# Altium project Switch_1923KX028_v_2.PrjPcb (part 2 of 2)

## Sheet switch_1923KX028_v_2_sheet_6.SchDoc
size A3; DocumentNumber: 7; SheetNumber: 7; SheetTotal: 10
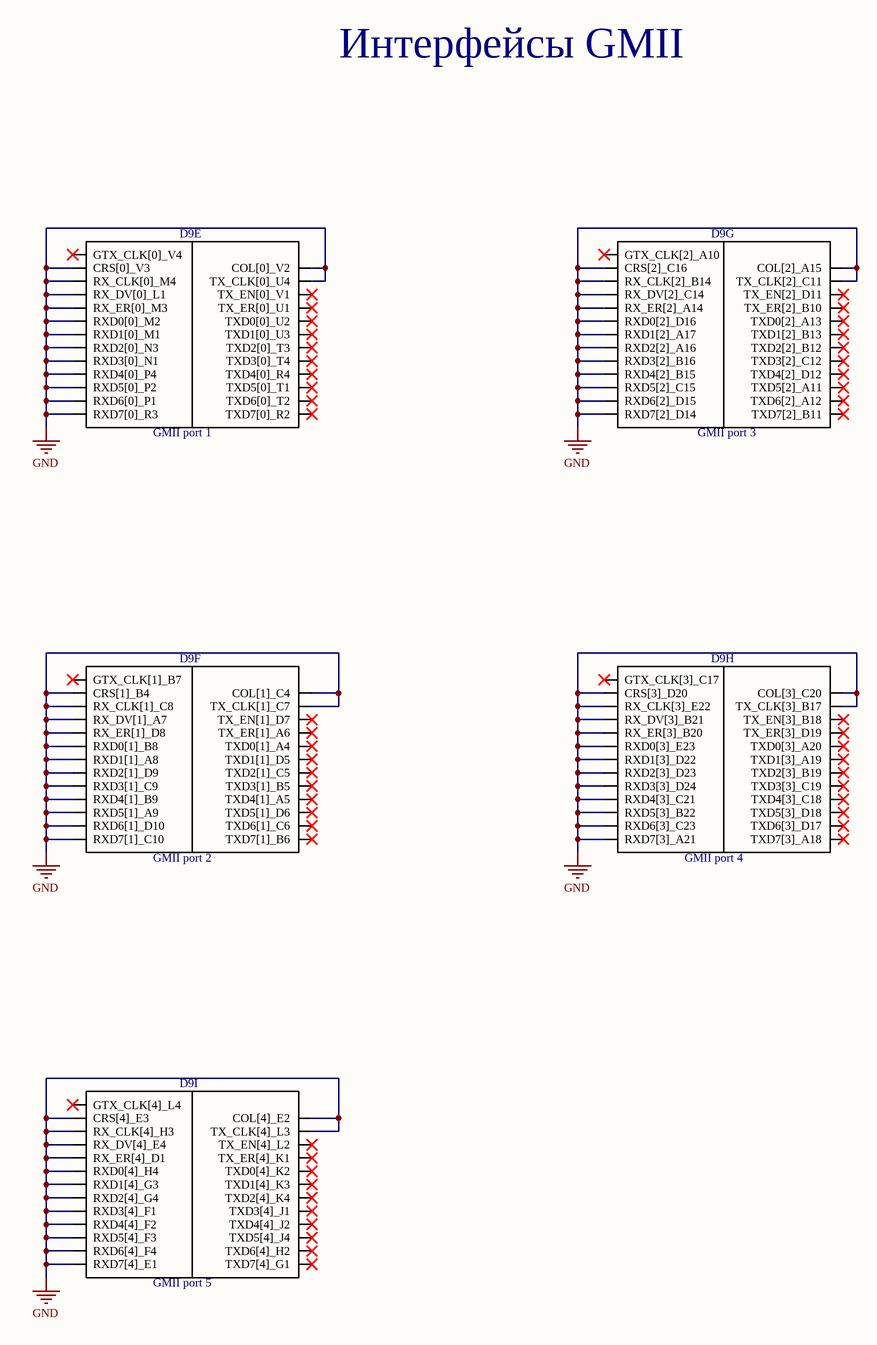
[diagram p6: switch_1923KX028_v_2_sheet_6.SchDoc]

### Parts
D9  1923KX028  [FOOTPRINT_MK8303.576-1]  (value not drawn)  (parts E,F,G,H,I of 27)

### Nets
GND: D9.A7(RX_DV[1]_A7) D9.A8(RXD1[1]_A8) D9.A9(RXD5[1]_A9) D9.A14(RX_ER[2]_A14) D9.A15(COL[2]_A15) D9.A16(RXD2[2]_A16) D9.A17(RXD1[2]_A17) D9.A21(RXD7[3]_A21) D9.B4(CRS[1]_B4) D9.B8(RXD0[1]_B8) D9.B9(RXD4[1]_B9) D9.B14(RX_CLK[2]_B14) D9.B15(RXD4[2]_B15) D9.B16(RXD3[2]_B16) D9.B17(TX_CLK[3]_B17) D9.B20(RX_ER[3]_B20) D9.B21(RX_DV[3]_B21) D9.B22(RXD5[3]_B22) D9.C4(COL[1]_C4) D9.C7(TX_CLK[1]_C7) D9.C8(RX_CLK[1]_C8) D9.C9(RXD3[1]_C9) D9.C10(RXD7[1]_C10) D9.C11(TX_CLK[2]_C11) D9.C14(RX_DV[2]_C14) D9.C15(RXD5[2]_C15) D9.C16(CRS[2]_C16) D9.C20(COL[3]_C20) D9.C21(RXD4[3]_C21) D9.C23(RXD6[3]_C23) D9.D1(RX_ER[4]_D1) D9.D8(RX_ER[1]_D8) D9.D9(RXD2[1]_D9) D9.D10(RXD6[1]_D10) D9.D14(RXD7[2]_D14) D9.D15(RXD6[2]_D15) D9.D16(RXD0[2]_D16) D9.D20(CRS[3]_D20) D9.D22(RXD1[3]_D22) D9.D23(RXD2[3]_D23) D9.D24(RXD3[3]_D24) D9.E1(RXD7[4]_E1) D9.E2(COL[4]_E2) D9.E3(CRS[4]_E3) D9.E4(RX_DV[4]_E4) D9.E22(RX_CLK[3]_E22) D9.E23(RXD0[3]_E23) D9.F1(RXD3[4]_F1) D9.F2(RXD4[4]_F2) D9.F3(RXD5[4]_F3) D9.F4(RXD6[4]_F4) D9.G3(RXD1[4]_G3) D9.G4(RXD2[4]_G4) D9.H3(RX_CLK[4]_H3) D9.H4(RXD0[4]_H4) D9.L1(RX_DV[0]_L1) D9.L3(TX_CLK[4]_L3) D9.M1(RXD1[0]_M1) D9.M2(RXD0[0]_M2) D9.M3(RX_ER[0]_M3) D9.M4(RX_CLK[0]_M4) D9.N1(RXD3[0]_N1) D9.N3(RXD2[0]_N3) D9.P1(RXD6[0]_P1) D9.P2(RXD5[0]_P2) D9.P4(RXD4[0]_P4) D9.R3(RXD7[0]_R3) D9.U4(TX_CLK[0]_U4) D9.V2(COL[0]_V2) D9.V3(CRS[0]_V3)

Not connected (* = marked no-connect by the designer): D9 A4(TXD0[1]_A4)* A5(TXD4[1]_A5)* A6(TX_ER[1]_A6)* A10(GTX_CLK[2]_A10)* A11(TXD5[2]_A11)* A12(TXD6[2]_A12)* A13(TXD0[2]_A13)* A18(TXD7[3]_A18)* A19(TXD1[3]_A19)* A20(TXD0[3]_A20)* B5(TXD3[1]_B5)* B6(TXD7[1]_B6)* B7(GTX_CLK[1]_B7)* B10(TX_ER[2]_B10)* B11(TXD7[2]_B11)* B12(TXD2[2]_B12)* B13(TXD1[2]_B13)* B18(TX_EN[3]_B18)* B19(TXD2[3]_B19)* C5(TXD2[1]_C5)* C6(TXD6[1]_C6)* C12(TXD3[2]_C12)* C17(GTX_CLK[3]_C17)* C18(TXD4[3]_C18)* C19(TXD3[3]_C19)* D5(TXD1[1]_D5)* D6(TXD5[1]_D6)* D7(TX_EN[1]_D7)* D11(TX_EN[2]_D11)* D12(TXD4[2]_D12)* D17(TXD6[3]_D17)* D18(TXD5[3]_D18)* D19(TX_ER[3]_D19)* G1(TXD7[4]_G1)* H2(TXD6[4]_H2)* J1(TXD3[4]_J1)* J2(TXD4[4]_J2)* J4(TXD5[4]_J4)* K1(TX_ER[4]_K1)* K2(TXD0[4]_K2)* K3(TXD1[4]_K3)* K4(TXD2[4]_K4)* L2(TX_EN[4]_L2)* L4(GTX_CLK[4]_L4)* R2(TXD7[0]_R2)* R4(TXD4[0]_R4)* T1(TXD5[0]_T1)* T2(TXD6[0]_T2)* T3(TXD2[0]_T3)* T4(TXD3[0]_T4)* U1(TX_ER[0]_U1)* U2(TXD0[0]_U2)* U3(TXD1[0]_U3)* V1(TX_EN[0]_V1)* V4(GTX_CLK[0]_V4)*

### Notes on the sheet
- Интерфейсы GMII

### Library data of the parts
D9 = 1923KX028: Milandr, 16 ports Ethernet Switch 1000/100/10

## Sheet switch_1923KX028_v_2_sheet_7.SchDoc
size A3; DocumentNumber: 8; SheetNumber: 8; SheetTotal: 10
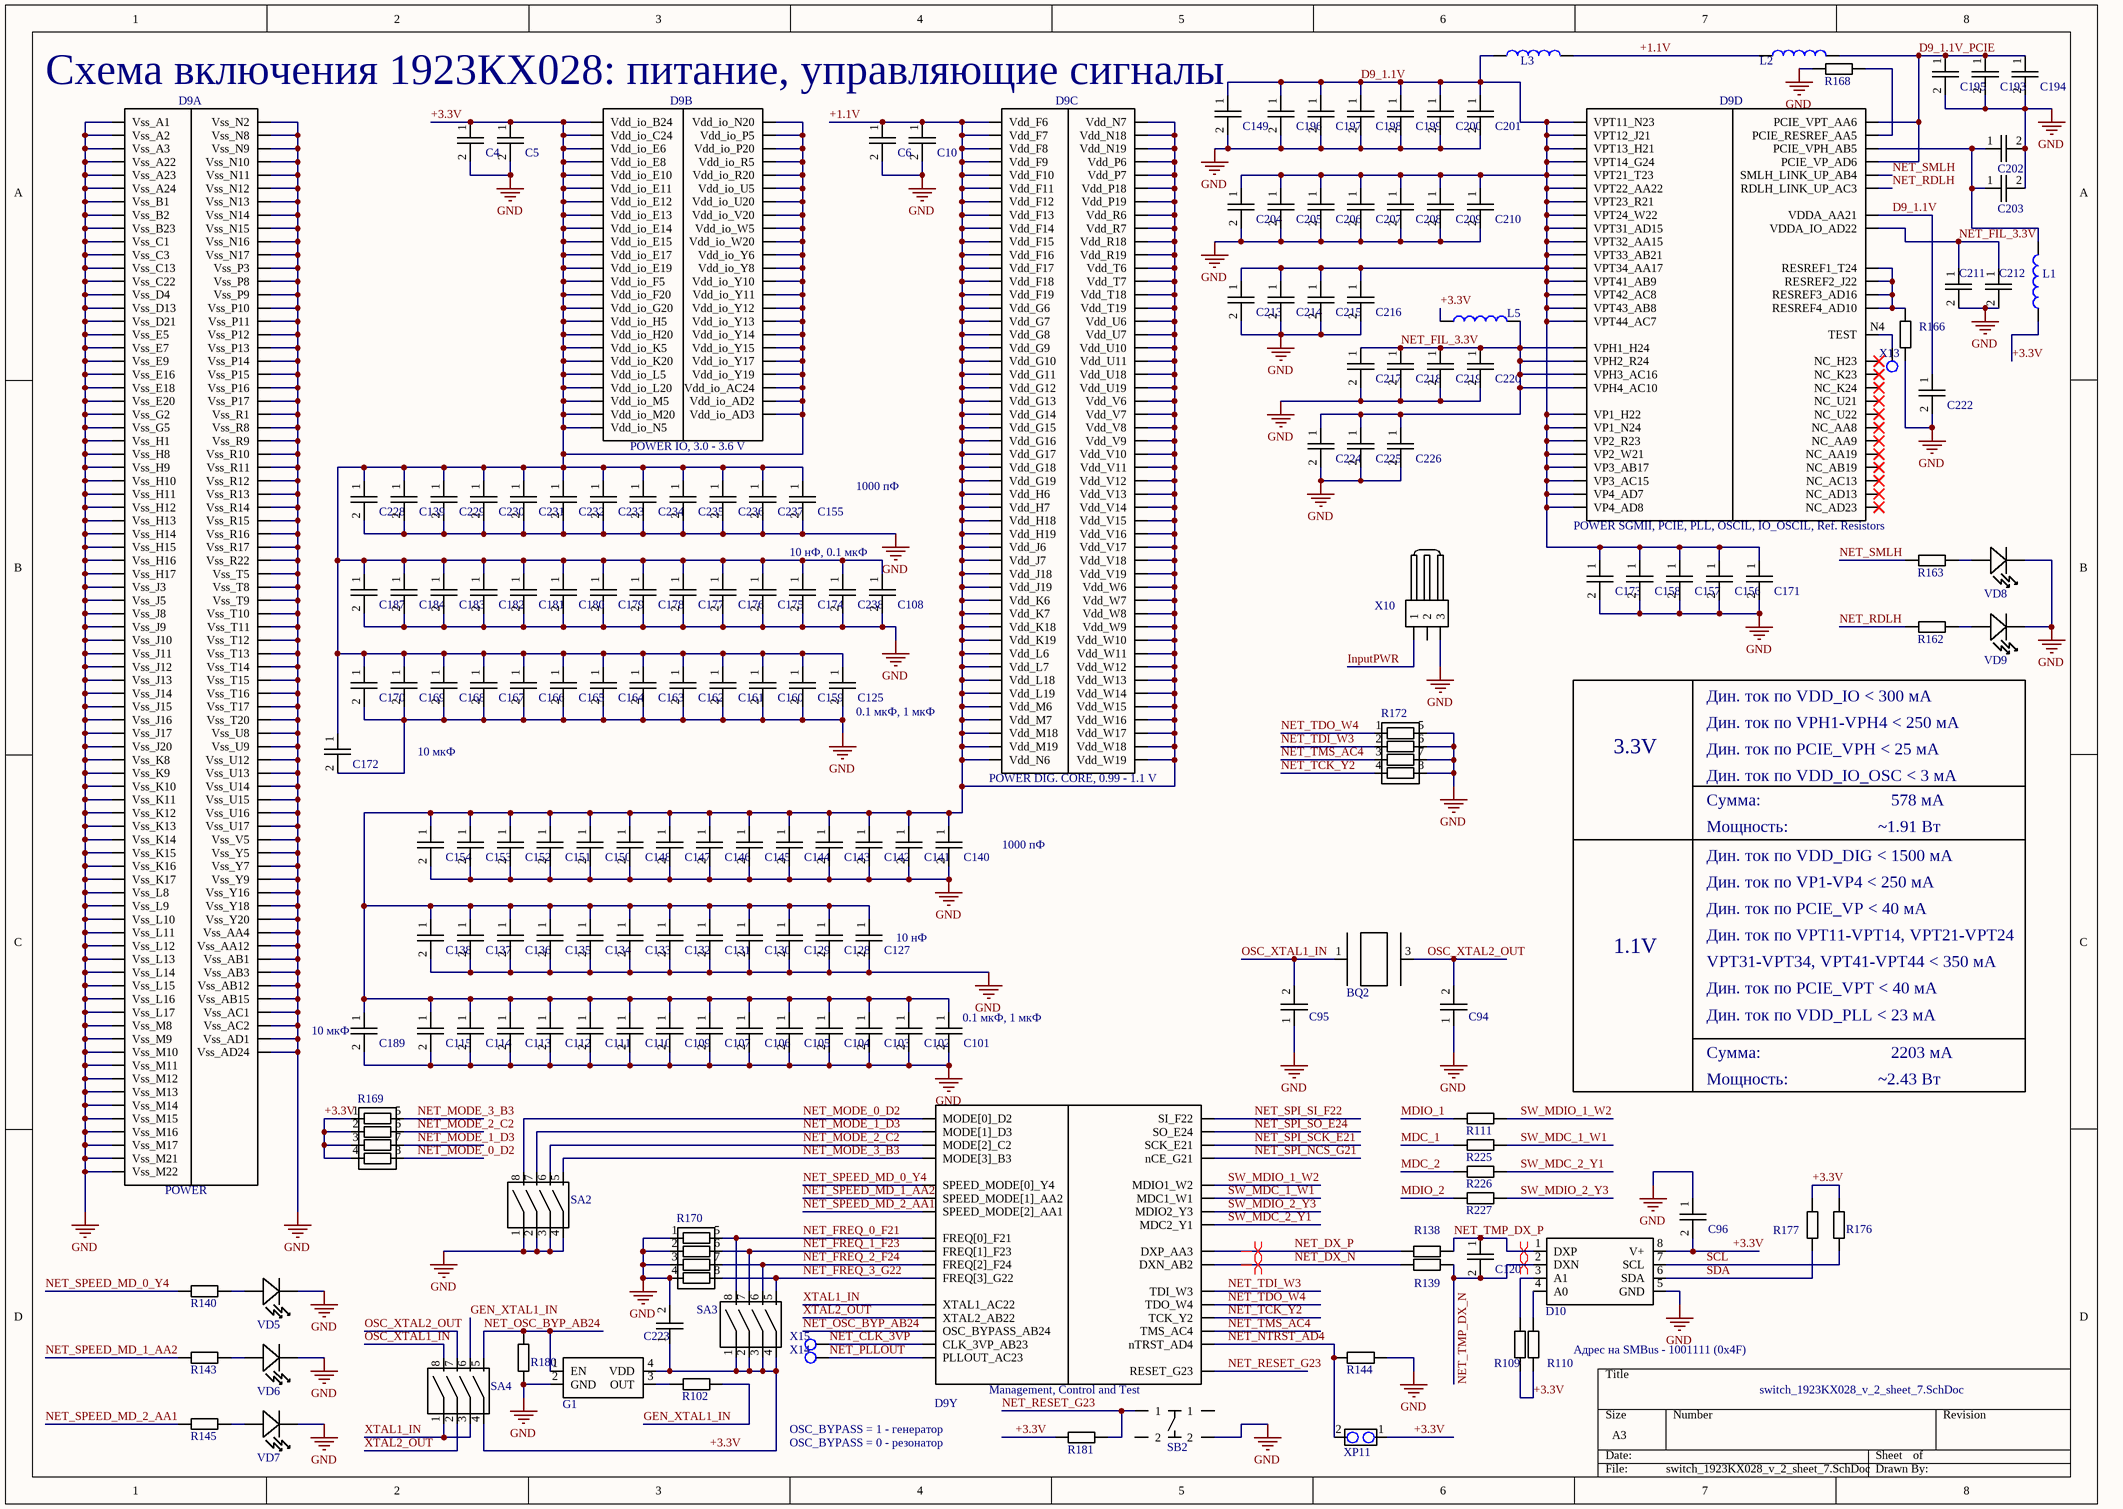
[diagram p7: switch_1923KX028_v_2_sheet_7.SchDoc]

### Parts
BQ2  25.0MHz, 30ppm, CL = 12pF, KX-7  [FOOTPRINT_KX7]  (value not drawn)
C4  100uF, X5R, 6.3В, 1206  [FOOTPRINT_1206]  (value not drawn)
C5  100uF, X5R, 6.3В, 1206  [FOOTPRINT_1206]  (value not drawn)
C6  100uF, X5R, 6.3В, 1206  [FOOTPRINT_1206]  (value not drawn)
C10  100uF, X5R, 6.3В, 1206  [FOOTPRINT_1206]  (value not drawn)
C94  18pF, 50V, C0G, 0402  [FOOTPRINT_0402]  (value not drawn)
C95  18pF, 50V, C0G, 0402  [FOOTPRINT_0402]  (value not drawn)
C96  100nF, 10V, X5R, 0402  [FOOTPRINT_0402]  (value not drawn)
C101  1.0uF, 10V, X5R, 0402  [FOOTPRINT_0402]  (value not drawn)
C102  1.0uF, 10V, X5R, 0402  [FOOTPRINT_0402]  (value not drawn)
C103  1.0uF, 10V, X5R, 0402  [FOOTPRINT_0402]  (value not drawn)
C104  1.0uF, 10V, X5R, 0402  [FOOTPRINT_0402]  (value not drawn)
C105  100nF, 10V, X5R, 0402  [FOOTPRINT_0402]  (value not drawn)
C106  100nF, 10V, X5R, 0402  [FOOTPRINT_0402]  (value not drawn)
C107  100nF, 10V, X5R, 0402  [FOOTPRINT_0402]  (value not drawn)
C108  10nF, 25V, X7R, 0402  [FOOTPRINT_0402]  (value not drawn)
C109  100nF, 10V, X5R, 0402  [FOOTPRINT_0402]  (value not drawn)
C110  100nF, 10V, X5R, 0402  [FOOTPRINT_0402]  (value not drawn)
C111  100nF, 10V, X5R, 0402  [FOOTPRINT_0402]  (value not drawn)
C112  100nF, 10V, X5R, 0402  [FOOTPRINT_0402]  (value not drawn)
C113  100nF, 10V, X5R, 0402  [FOOTPRINT_0402]  (value not drawn)
C114  100nF, 10V, X5R, 0402  [FOOTPRINT_0402]  (value not drawn)
C115  100nF, 10V, X5R, 0402  [FOOTPRINT_0402]  (value not drawn)
C120  100pF, 50V, C0G, 0402  [FOOTPRINT_0402]  (value not drawn)
C125  100nF, 10V, X5R, 0402  [FOOTPRINT_0402]  (value not drawn)
C127  10nF, 25V, X7R, 0402  [FOOTPRINT_0402]  (value not drawn)
C128  10nF, 25V, X7R, 0402  [FOOTPRINT_0402]  (value not drawn)
C129  10nF, 25V, X7R, 0402  [FOOTPRINT_0402]  (value not drawn)
C130  10nF, 25V, X7R, 0402  [FOOTPRINT_0402]  (value not drawn)
C131  10nF, 25V, X7R, 0402  [FOOTPRINT_0402]  (value not drawn)
C132  10nF, 25V, X7R, 0402  [FOOTPRINT_0402]  (value not drawn)
C133  10nF, 25V, X7R, 0402  [FOOTPRINT_0402]  (value not drawn)
C134  10nF, 25V, X7R, 0402  [FOOTPRINT_0402]  (value not drawn)
C135  10nF, 25V, X7R, 0402  [FOOTPRINT_0402]  (value not drawn)
C136  10nF, 25V, X7R, 0402  [FOOTPRINT_0402]  (value not drawn)
C137  10nF, 25V, X7R, 0402  [FOOTPRINT_0402]  (value not drawn)
C138  10nF, 25V, X7R, 0402  [FOOTPRINT_0402]  (value not drawn)
C139  1nF, 50V, X7R, 0402  [FOOTPRINT_0402]  (value not drawn)
C140  1nF, 50V, X7R, 0402  [FOOTPRINT_0402]  (value not drawn)
C141  1nF, 50V, X7R, 0402  [FOOTPRINT_0402]  (value not drawn)
C142  1nF, 50V, X7R, 0402  [FOOTPRINT_0402]  (value not drawn)
C143  1nF, 50V, X7R, 0402  [FOOTPRINT_0402]  (value not drawn)
C144  1nF, 50V, X7R, 0402  [FOOTPRINT_0402]  (value not drawn)
C145  1nF, 50V, X7R, 0402  [FOOTPRINT_0402]  (value not drawn)
C146  1nF, 50V, X7R, 0402  [FOOTPRINT_0402]  (value not drawn)
C147  1nF, 50V, X7R, 0402  [FOOTPRINT_0402]  (value not drawn)
C148  1nF, 50V, X7R, 0402  [FOOTPRINT_0402]  (value not drawn)
C149  10 uF, 10%, 25V, X5R, 1206  [FOOTPRINT_1206]  (value not drawn)
C150  1nF, 50V, X7R, 0402  [FOOTPRINT_0402]  (value not drawn)
C151  1nF, 50V, X7R, 0402  [FOOTPRINT_0402]  (value not drawn)
C152  1nF, 50V, X7R, 0402  [FOOTPRINT_0402]  (value not drawn)
C153  1nF, 50V, X7R, 0402  [FOOTPRINT_0402]  (value not drawn)
C154  1nF, 50V, X7R, 0402  [FOOTPRINT_0402]  (value not drawn)
C155  1nF, 50V, X7R, 0402  [FOOTPRINT_0402]  (value not drawn)
C156  1.0uF, 10V, X5R, 0402  [FOOTPRINT_0402]  (value not drawn)
C157  1.0uF, 10V, X5R, 0402  [FOOTPRINT_0402]  (value not drawn)
C158  1.0uF, 10V, X5R, 0402  [FOOTPRINT_0402]  (value not drawn)
C159  1.0uF, 10V, X5R, 0402  [FOOTPRINT_0402]  (value not drawn)
C160  1.0uF, 10V, X5R, 0402  [FOOTPRINT_0402]  (value not drawn)
C161  1.0uF, 10V, X5R, 0402  [FOOTPRINT_0402]  (value not drawn)
C162  1.0uF, 10V, X5R, 0402  [FOOTPRINT_0402]  (value not drawn)
C163  1.0uF, 10V, X5R, 0402  [FOOTPRINT_0402]  (value not drawn)
C164  1.0uF, 10V, X5R, 0402  [FOOTPRINT_0402]  (value not drawn)
C165  100nF, 10V, X5R, 0402  [FOOTPRINT_0402]  (value not drawn)
C166  100nF, 10V, X5R, 0402  [FOOTPRINT_0402]  (value not drawn)
C167  100nF, 10V, X5R, 0402  [FOOTPRINT_0402]  (value not drawn)
C168  100nF, 10V, X5R, 0402  [FOOTPRINT_0402]  (value not drawn)
C169  100nF, 10V, X5R, 0402  [FOOTPRINT_0402]  (value not drawn)
C170  100nF, 10V, X5R, 0402  [FOOTPRINT_0402]  (value not drawn)
C171  10 uF, 10%, 25V, X5R, 1206  [FOOTPRINT_1206]  (value not drawn)
C172  10 uF, 10%, 25V, X5R, 1206  [FOOTPRINT_1206]  (value not drawn)
C173  100nF, 10V, X5R, 0402  [FOOTPRINT_0402]  (value not drawn)
C174  100nF, 10V, X5R, 0402  [FOOTPRINT_0402]  (value not drawn)
C175  100nF, 10V, X5R, 0402  [FOOTPRINT_0402]  (value not drawn)
C176  100nF, 10V, X5R, 0402  [FOOTPRINT_0402]  (value not drawn)
C177  100nF, 10V, X5R, 0402  [FOOTPRINT_0402]  (value not drawn)
C178  100nF, 10V, X5R, 0402  [FOOTPRINT_0402]  (value not drawn)
C179  100nF, 10V, X5R, 0402  [FOOTPRINT_0402]  (value not drawn)
C180  10nF, 25V, X7R, 0402  [FOOTPRINT_0402]  (value not drawn)
C181  10nF, 25V, X7R, 0402  [FOOTPRINT_0402]  (value not drawn)
C182  10nF, 25V, X7R, 0402  [FOOTPRINT_0402]  (value not drawn)
C183  10nF, 25V, X7R, 0402  [FOOTPRINT_0402]  (value not drawn)
C184  10nF, 25V, X7R, 0402  [FOOTPRINT_0402]  (value not drawn)
C187  10nF, 25V, X7R, 0402  [FOOTPRINT_0402]  (value not drawn)
C189  10 uF, 10%, 25V, X5R, 1206  [FOOTPRINT_1206]  (value not drawn)
C193  1nF, 50V, X7R, 0402  [FOOTPRINT_0402]  (value not drawn)
C194  100nF, 10V, X5R, 0402  [FOOTPRINT_0402]  (value not drawn)
C195  1.0uF, 10V, X5R, 0402  [FOOTPRINT_0402]  (value not drawn)
C196  1nF, 50V, X7R, 0402  [FOOTPRINT_0402]  (value not drawn)
C197  1nF, 50V, X7R, 0402  [FOOTPRINT_0402]  (value not drawn)
C198  1nF, 50V, X7R, 0402  [FOOTPRINT_0402]  (value not drawn)
C199  1nF, 50V, X7R, 0402  [FOOTPRINT_0402]  (value not drawn)
C200  1nF, 50V, X7R, 0402  [FOOTPRINT_0402]  (value not drawn)
C201  1nF, 50V, X7R, 0402  [FOOTPRINT_0402]  (value not drawn)
C202  100nF, 10V, X5R, 0402  [FOOTPRINT_0402]  (value not drawn)
C203  1nF, 50V, X7R, 0402  [FOOTPRINT_0402]  (value not drawn)
C204  100nF, 10V, X5R, 0402  [FOOTPRINT_0402]  (value not drawn)
C205  100nF, 10V, X5R, 0402  [FOOTPRINT_0402]  (value not drawn)
C206  100nF, 10V, X5R, 0402  [FOOTPRINT_0402]  (value not drawn)
C207  100nF, 10V, X5R, 0402  [FOOTPRINT_0402]  (value not drawn)
C208  100nF, 10V, X5R, 0402  [FOOTPRINT_0402]  (value not drawn)
C209  100nF, 10V, X5R, 0402  [FOOTPRINT_0402]  (value not drawn)
C210  100nF, 10V, X5R, 0402  [FOOTPRINT_0402]  (value not drawn)
C211  1nF, 50V, X7R, 0402  [FOOTPRINT_0402]  (value not drawn)
C212  100nF, 10V, X5R, 0402  [FOOTPRINT_0402]  (value not drawn)
C213  1.0uF, 10V, X5R, 0402  [FOOTPRINT_0402]  (value not drawn)
C214  1.0uF, 10V, X5R, 0402  [FOOTPRINT_0402]  (value not drawn)
C215  1.0uF, 10V, X5R, 0402  [FOOTPRINT_0402]  (value not drawn)
C216  1.0uF, 10V, X5R, 0402  [FOOTPRINT_0402]  (value not drawn)
C217  100nF, 10V, X5R, 0402  [FOOTPRINT_0402]  (value not drawn)
C218  100nF, 10V, X5R, 0402  [FOOTPRINT_0402]  (value not drawn)
C219  100nF, 10V, X5R, 0402  [FOOTPRINT_0402]  (value not drawn)
C220  100nF, 10V, X5R, 0402  [FOOTPRINT_0402]  (value not drawn)
C222  100nF, 10V, X5R, 0402  [FOOTPRINT_0402]  (value not drawn)
C223  100nF, 10V, X5R, 0402  [FOOTPRINT_0402]  (value not drawn)
C224  1nF, 50V, X7R, 0402  [FOOTPRINT_0402]  (value not drawn)
C225  1nF, 50V, X7R, 0402  [FOOTPRINT_0402]  (value not drawn)
C226  1nF, 50V, X7R, 0402  [FOOTPRINT_0402]  (value not drawn)
C228  1nF, 50V, X7R, 0402  [FOOTPRINT_0402]  (value not drawn)
C229  1nF, 50V, X7R, 0402  [FOOTPRINT_0402]  (value not drawn)
C230  1nF, 50V, X7R, 0402  [FOOTPRINT_0402]  (value not drawn)
C231  1nF, 50V, X7R, 0402  [FOOTPRINT_0402]  (value not drawn)
C232  1nF, 50V, X7R, 0402  [FOOTPRINT_0402]  (value not drawn)
C233  1nF, 50V, X7R, 0402  [FOOTPRINT_0402]  (value not drawn)
C234  1nF, 50V, X7R, 0402  [FOOTPRINT_0402]  (value not drawn)
C235  1nF, 50V, X7R, 0402  [FOOTPRINT_0402]  (value not drawn)
C236  1nF, 50V, X7R, 0402  [FOOTPRINT_0402]  (value not drawn)
C237  1nF, 50V, X7R, 0402  [FOOTPRINT_0402]  (value not drawn)
C238  100nF, 10V, X5R, 0402  [FOOTPRINT_0402]  (value not drawn)
D9  1923KX028  [FOOTPRINT_MK8303.576-1]  (value not drawn)  (parts A,B,C,D,Y of 27)
D10  TMP421, SOT-23  [SOT-23]  (value not drawn)
G1  25.0 MHz, +3.3V  [FOOTPRINT_KX7]  (value not drawn)
L1  0805  [FOOTPRINT_0805]  (value not drawn)
L2  0805  [FOOTPRINT_0805]  (value not drawn)
L3  0805  [FOOTPRINT_0805]  (value not drawn)
L5  0805  [FOOTPRINT_0805]  (value not drawn)
R102  24, 1%, 0402  [FOOTPRINT_0402]  (value not drawn)
R109  11K, 1%, 0402  [FOOTPRINT_0402]  (value not drawn)
R110  11K, 1%, 0402  [FOOTPRINT_0402]  (value not drawn)
R111  24, 1%, 0402  [FOOTPRINT_0402]  (value not drawn)
R138  49.9, 1%, 0402  [FOOTPRINT_0402]  (value not drawn)
R139  49.9, 1%, 0402  [FOOTPRINT_0402]  (value not drawn)
R140  280 1% 0402  [FOOTPRINT_0402]  (value not drawn)
R143  280 1% 0402  [FOOTPRINT_0402]  (value not drawn)
R144  11K, 1%, 0402  [FOOTPRINT_0402]  (value not drawn)
R145  280 1% 0402  [FOOTPRINT_0402]  (value not drawn)
R162  280 1% 0402  [FOOTPRINT_0402]  (value not drawn)
R163  280 1% 0402  [FOOTPRINT_0402]  (value not drawn)
R166  200, 1%, 0402  [FOOTPRINT_0402]  (value not drawn)
R168  200, 1%, 0402  [FOOTPRINT_0402]  (value not drawn)
R169  4 x 10K, 5%, 0804  [FOOTPRINT_0804_RES_ARRAY]  (value not drawn)
R170  4 x 10K, 5%, 0804  [FOOTPRINT_0804_RES_ARRAY]  (value not drawn)
R172  4 x 10K, 5%, 0804  [FOOTPRINT_0804_RES_ARRAY]  (value not drawn)
R176  11K, 1%, 0402  [FOOTPRINT_0402]  (value not drawn)
R177  11K, 1%, 0402  [FOOTPRINT_0402]  (value not drawn)
R180  11K, 1%, 0402  [FOOTPRINT_0402]  (value not drawn)
R181  11K, 1%, 0402  [FOOTPRINT_0402]  (value not drawn)
R225  24, 1%, 0402  [FOOTPRINT_0402]  (value not drawn)
R226  24, 1%, 0402  [FOOTPRINT_0402]  (value not drawn)
R227  24, 1%, 0402  [FOOTPRINT_0402]  (value not drawn)
SA2  DMHA-04G-G  [FOOTPRINT_DMHA-04G-G]  (value not drawn)
SA3  DMHA-04G-G  [FOOTPRINT_DMHA-04G-G]  (value not drawn)
SA4  DMHA-04G-G  [FOOTPRINT_DMHA-04G-G]  (value not drawn)
SB2  7914G-1-000 Е  [7914G_1_000_E]  (value not drawn)
VD5  KP-2012SYCK  [FOOTPRINT_SMD_LED_2.0x1.25mm]  (value not drawn)
VD6  KP-2012SYCK  [FOOTPRINT_SMD_LED_2.0x1.25mm]  (value not drawn)
VD7  KP-2012SYCK  [FOOTPRINT_SMD_LED_2.0x1.25mm]  (value not drawn)
VD8  KP-2012SYCK  [FOOTPRINT_SMD_LED_2.0x1.25mm]  (value not drawn)
VD9  KP-2012SYCK  [FOOTPRINT_SMD_LED_2.0x1.25mm]  (value not drawn)
X10  WF-3  [FOOTPRINT_WF-3]  (value not drawn)
X13  hole d=1mm  [FOOTPRINT_TESTPOINT]  (value not drawn)
X14  hole d=1mm  [FOOTPRINT_TESTPOINT]  (value not drawn)
X15  hole d=1mm  [FOOTPRINT_TESTPOINT]  (value not drawn)
XP11  PLS-2  [PLS-2]  (value not drawn)

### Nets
+1.1V: C6.1 C10.1 C101.1 C102.1 C103.1 C104.1 C105.1 C106.1 C107.1 C109.1 C110.1 C111.1 C112.1 C113.1 C114.1 C115.1 C127.1 C128.1 C129.1 C130.1 C131.1 C132.1 C133.1 C134.1 C135.1 C136.1 C137.1 C138.1 C140.1 C141.1 C142.1 C143.1 C144.1 C145.1 C146.1 C147.1 C148.1 C150.1 C151.1 C152.1 C153.1 C154.1 C189.1 D9.F6(Vdd_F6) D9.F7(Vdd_F7) D9.F8(Vdd_F8) D9.F9(Vdd_F9) D9.F10(Vdd_F10) D9.F11(Vdd_F11) D9.F12(Vdd_F12) D9.F13(Vdd_F13) D9.F14(Vdd_F14) D9.F15(Vdd_F15) D9.F16(Vdd_F16) D9.F17(Vdd_F17) D9.F18(Vdd_F18) D9.F19(Vdd_F19) D9.G6(Vdd_G6) D9.G7(Vdd_G7) D9.G8(Vdd_G8) D9.G9(Vdd_G9) D9.G10(Vdd_G10) D9.G11(Vdd_G11) D9.G12(Vdd_G12) D9.G13(Vdd_G13) D9.G14(Vdd_G14) D9.G15(Vdd_G15) D9.G16(Vdd_G16) D9.G17(Vdd_G17) D9.G18(Vdd_G18) D9.G19(Vdd_G19) D9.H6(Vdd_H6) D9.H7(Vdd_H7) D9.H18(Vdd_H18) D9.H19(Vdd_H19) D9.J6(Vdd_J6) D9.J7(Vdd_J7) D9.J18(Vdd_J18) D9.J19(Vdd_J19) D9.K6(Vdd_K6) D9.K7(Vdd_K7) D9.K18(Vdd_K18) D9.K19(Vdd_K19) D9.L6(Vdd_L6) D9.L7(Vdd_L7) D9.L18(Vdd_L18) D9.L19(Vdd_L19) D9.M6(Vdd_M6) D9.M7(Vdd_M7) D9.M18(Vdd_M18) D9.M19(Vdd_M19) D9.N6(Vdd_N6) D9.N7(Vdd_N7) D9.N18(Vdd_N18) D9.N19(Vdd_N19) D9.P6(Vdd_P6) D9.P7(Vdd_P7) D9.P18(Vdd_P18) D9.P19(Vdd_P19) D9.R6(Vdd_R6) D9.R7(Vdd_R7) D9.R18(Vdd_R18) D9.R19(Vdd_R19) D9.T6(Vdd_T6) D9.T7(Vdd_T7) D9.T18(Vdd_T18) D9.T19(Vdd_T19) D9.U6(Vdd_U6) D9.U7(Vdd_U7) D9.U10(Vdd_U10) D9.U11(Vdd_U11) D9.U18(Vdd_U18) D9.U19(Vdd_U19) D9.V6(Vdd_V6) D9.V7(Vdd_V7) D9.V8(Vdd_V8) D9.V9(Vdd_V9) D9.V10(Vdd_V10) D9.V11(Vdd_V11) D9.V12(Vdd_V12) D9.V13(Vdd_V13) D9.V14(Vdd_V14) D9.V15(Vdd_V15) D9.V16(Vdd_V16) D9.V17(Vdd_V17) D9.V18(Vdd_V18) D9.V19(Vdd_V19) D9.W6(Vdd_W6) D9.W7(Vdd_W7) D9.W8(Vdd_W8) D9.W9(Vdd_W9) D9.W10(Vdd_W10) D9.W11(Vdd_W11) D9.W12(Vdd_W12) D9.W13(Vdd_W13) D9.W14(Vdd_W14) D9.W15(Vdd_W15) D9.W16(Vdd_W16) D9.W17(Vdd_W17) D9.W18(Vdd_W18) D9.W19(Vdd_W19) L2.1 L3.2
+3.3V: C4.1 C5.1 C96.2 C108.1 C125.1 C139.1 C155.1 C159.1 C160.1 C161.1 C162.1 C163.1 C164.1 C165.1 C166.1 C167.1 C168.1 C169.1 C170.1 C172.1 C174.1 C175.1 C176.1 C177.1 C178.1 C179.1 C180.1 C181.1 C182.1 C183.1 C184.1 C187.1 C223.1 C228.1 C229.1 C230.1 C231.1 C232.1 C233.1 C234.1 C235.1 C236.1 C237.1 C238.1 D9.AC24(Vdd_io_AC24) D9.AD2(Vdd_io_AD2) D9.AD3(Vdd_io_AD3) D9.B24(Vdd_io_B24) D9.C24(Vdd_io_C24) D9.E6(Vdd_io_E6) D9.E8(Vdd_io_E8) D9.E10(Vdd_io_E10) D9.E11(Vdd_io_E11) D9.E12(Vdd_io_E12) D9.E13(Vdd_io_E13) D9.E14(Vdd_io_E14) D9.E15(Vdd_io_E15) D9.E17(Vdd_io_E17) D9.E19(Vdd_io_E19) D9.F5(Vdd_io_F5) D9.F20(Vdd_io_F20) D9.G20(Vdd_io_G20) D9.H5(Vdd_io_H5) D9.H20(Vdd_io_H20) D9.K5(Vdd_io_K5) D9.K20(Vdd_io_K20) D9.L5(Vdd_io_L5) D9.L20(Vdd_io_L20) D9.M5(Vdd_io_M5) D9.M20(Vdd_io_M20) D9.N5(Vdd_io_N5) D9.N20(Vdd_io_N20) D9.P5(Vdd_io_P5) D9.P20(Vdd_io_P20) D9.R5(Vdd_io_R5) D9.R20(Vdd_io_R20) D9.U5(Vdd_io_U5) D9.U20(Vdd_io_U20) D9.V20(Vdd_io_V20) D9.W5(Vdd_io_W5) D9.W20(Vdd_io_W20) D9.Y6(Vdd_io_Y6) D9.Y8(Vdd_io_Y8) D9.Y10(Vdd_io_Y10) D9.Y11(Vdd_io_Y11) D9.Y12(Vdd_io_Y12) D9.Y13(Vdd_io_Y13) D9.Y14(Vdd_io_Y14) D9.Y15(Vdd_io_Y15) D9.Y17(Vdd_io_Y17) D9.Y19(Vdd_io_Y19) D10.8(V+) G1.4(VDD) L1.1 L5.1 R109.2 R110.2 R169.1 R169.2 R169.3 R169.4 R176.2 R177.2 R181.1 SA3.1 SA3.2 SA3.3 SA3.4 SA4.4 XP11.1
GND: C4.2 C5.2 C6.2 C10.2 C94.1 C95.1 C96.1 C101.2 C102.2 C103.2 C104.2 C105.2 C106.2 C107.2 C108.2 C109.2 C110.2 C111.2 C112.2 C113.2 C114.2 C115.2 C125.2 C127.2 C128.2 C129.2 C130.2 C131.2 C132.2 C133.2 C134.2 C135.2 C136.2 C137.2 C138.2 C139.2 C140.2 C141.2 C142.2 C143.2 C144.2 C145.2 C146.2 C147.2 C148.2 C149.2 C150.2 C151.2 C152.2 C153.2 C154.2 C155.2 C156.2 C157.2 C158.2 C159.2 C160.2 C161.2 C162.2 C163.2 C164.2 C165.2 C166.2 C167.2 C168.2 C169.2 C170.2 C171.2 C172.2 C173.2 C174.2 C175.2 C176.2 C177.2 C178.2 C179.2 C180.2 C181.2 C182.2 C183.2 C184.2 C187.2 C189.2 C193.2 C194.2 C195.2 C196.2 C197.2 C198.2 C199.2 C200.2 C201.2 C202.2 C203.2 C204.2 C205.2 C206.2 C207.2 C208.2 C209.2 C210.2 C211.2 C212.2 C213.2 C214.2 C215.2 C216.2 C217.2 C218.2 C219.2 C220.2 C222.2 C223.2 C224.2 C225.2 C226.2 C228.2 C229.2 C230.2 C231.2 C232.2 C233.2 C234.2 C235.2 C236.2 C237.2 C238.2 D9.A1(Vss_A1) D9.A2(Vss_A2) D9.A3(Vss_A3) D9.A22(Vss_A22) D9.A23(Vss_A23) D9.A24(Vss_A24) D9.AA4(Vss_AA4) D9.AA12(Vss_AA12) D9.AB1(Vss_AB1) D9.AB3(Vss_AB3) D9.AB12(Vss_AB12) D9.AB15(Vss_AB15) D9.AC1(Vss_AC1) D9.AC2(Vss_AC2) D9.AD1(Vss_AD1) D9.AD24(Vss_AD24) D9.B1(Vss_B1) D9.B2(Vss_B2) D9.B23(Vss_B23) D9.C1(Vss_C1) D9.C3(Vss_C3) D9.C13(Vss_C13) D9.C22(Vss_C22) D9.D4(Vss_D4) D9.D13(Vss_D13) D9.D21(Vss_D21) D9.E5(Vss_E5) D9.E7(Vss_E7) D9.E9(Vss_E9) D9.E16(Vss_E16) D9.E18(Vss_E18) D9.E20(Vss_E20) D9.G2(Vss_G2) D9.G5(Vss_G5) D9.H1(Vss_H1) D9.H8(Vss_H8) D9.H9(Vss_H9) D9.H10(Vss_H10) D9.H11(Vss_H11) D9.H12(Vss_H12) D9.H13(Vss_H13) D9.H14(Vss_H14) D9.H15(Vss_H15) D9.H16(Vss_H16) D9.H17(Vss_H17) D9.J3(Vss_J3) D9.J5(Vss_J5) D9.J8(Vss_J8) D9.J9(Vss_J9) D9.J10(Vss_J10) D9.J11(Vss_J11) D9.J12(Vss_J12) D9.J13(Vss_J13) D9.J14(Vss_J14) D9.J15(Vss_J15) D9.J16(Vss_J16) D9.J17(Vss_J17) D9.J20(Vss_J20) D9.K8(Vss_K8) D9.K9(Vss_K9) D9.K10(Vss_K10) D9.K11(Vss_K11) D9.K12(Vss_K12) D9.K13(Vss_K13) D9.K14(Vss_K14) D9.K15(Vss_K15) D9.K16(Vss_K16) D9.K17(Vss_K17) D9.L8(Vss_L8) D9.L9(Vss_L9) D9.L10(Vss_L10) D9.L11(Vss_L11) D9.L12(Vss_L12) D9.L13(Vss_L13) D9.L14(Vss_L14) D9.L15(Vss_L15) D9.L16(Vss_L16) D9.L17(Vss_L17) D9.M8(Vss_M8) D9.M9(Vss_M9) D9.M10(Vss_M10) D9.M11(Vss_M11) D9.M12(Vss_M12) D9.M13(Vss_M13) D9.M14(Vss_M14) D9.M15(Vss_M15) D9.M16(Vss_M16) D9.M17(Vss_M17) D9.M21(Vss_M21) D9.M22(Vss_M22) D9.N2(Vss_N2) D9.N8(Vss_N8) D9.N9(Vss_N9) D9.N10(Vss_N10) D9.N11(Vss_N11) D9.N12(Vss_N12) D9.N13(Vss_N13) D9.N14(Vss_N14) D9.N15(Vss_N15) D9.N16(Vss_N16) D9.N17(Vss_N17) D9.P3(Vss_P3) D9.P8(Vss_P8) D9.P9(Vss_P9) D9.P10(Vss_P10) D9.P11(Vss_P11) D9.P12(Vss_P12) D9.P13(Vss_P13) D9.P14(Vss_P14) D9.P15(Vss_P15) D9.P16(Vss_P16) D9.P17(Vss_P17) D9.R1(Vss_R1) D9.R8(Vss_R8) D9.R9(Vss_R9) D9.R10(Vss_R10) D9.R11(Vss_R11) D9.R12(Vss_R12) D9.R13(Vss_R13) D9.R14(Vss_R14) D9.R15(Vss_R15) D9.R16(Vss_R16) D9.R17(Vss_R17) D9.R22(Vss_R22) D9.T5(Vss_T5) D9.T8(Vss_T8) D9.T9(Vss_T9) D9.T10(Vss_T10) D9.T11(Vss_T11) D9.T12(Vss_T12) D9.T13(Vss_T13) D9.T14(Vss_T14) D9.T15(Vss_T15) D9.T16(Vss_T16) D9.T17(Vss_T17) D9.T20(Vss_T20) D9.U8(Vss_U8) D9.U9(Vss_U9) D9.U12(Vss_U12) D9.U13(Vss_U13) D9.U14(Vss_U14) D9.U15(Vss_U15) D9.U16(Vss_U16) D9.U17(Vss_U17) D9.V5(Vss_V5) D9.Y5(Vss_Y5) D9.Y7(Vss_Y7) D9.Y9(Vss_Y9) D9.Y16(Vss_Y16) D9.Y18(Vss_Y18) D9.Y20(Vss_Y20) D10.5(GND) G1.2(GND) R144.2 R166.2 R168.2 R170.1 R170.2 R170.3 R170.4 R172.5 R172.6 R172.7 R172.8 R180.1 SA2.1 SA2.2 SA2.3 SA2.4 SB2.3(2) VD5.2(C) VD6.2(C) VD7.2(C) VD8.2(C) VD9.2(C) X10.3
D9_1.1V: C149.1 C156.1 C157.1 C158.1 C171.1 C173.1 C196.1 C197.1 C198.1 C199.1 C200.1 C201.1 C204.1 C205.1 C206.1 C207.1 C208.1 C209.1 C210.1 C213.1 C214.1 C215.1 C216.1 C222.1 D9.AA15(VPT32_AA15) D9.AA17(VPT34_AA17) D9.AA21(VDDA_AA21) D9.AA22(VPT22_AA22) D9.AB8(VPT43_AB8) D9.AB9(VPT41_AB9) D9.AB17(VP3_AB17) D9.AB21(VPT33_AB21) D9.AC7(VPT44_AC7) D9.AC8(VPT42_AC8) D9.AC15(VP3_AC15) D9.AD7(VP4_AD7) D9.AD8(VP4_AD8) D9.AD15(VPT31_AD15) D9.G24(VPT14_G24) D9.H21(VPT13_H21) D9.H22(VP1_H22) D9.J21(VPT12_J21) D9.N23(VPT11_N23) D9.N24(VP1_N24) D9.R21(VPT23_R21) D9.R23(VP2_R23) D9.T23(VPT21_T23) D9.W21(VP2_W21) D9.W22(VPT24_W22) L3.1
D9_1.1V_PCIE: C193.1 C194.1 C195.1 D9.AA6(PCIE_VPT_AA6) D9.AD6(PCIE_VP_AD6) L2.2
GEN_XTAL1_IN: R102.1 SA4.6
InputPWR: X10.1
MDC_1: R225.2
MDC_2: R226.2
MDIO_1: R111.2
MDIO_2: R227.2
NET_CLK_3VP: D9.AB23(CLK_3VP_AB23) X15.1
NET_DX_N: D9.AB2(DXN_AB2) R139.2
NET_DX_P: D9.AA3(DXP_AA3) R138.2
NET_FIL_3.3V: C211.1 C212.1 C217.1 C218.1 C219.1 C220.1 C224.1 C225.1 C226.1 D9.AC10(VPH4_AC10) D9.AC16(VPH3_AC16) D9.AD22(VDDA_IO_AD22) D9.H24(VPH1_H24) D9.R24(VPH2_R24) L5.2
NET_FREQ_0_F21: D9.F21(FREQ[0]_F21) R170.5 SA3.8
NET_FREQ_1_F23: D9.F23(FREQ[1]_F23) R170.6 SA3.7
NET_FREQ_2_F24: D9.F24(FREQ[2]_F24) R170.7 SA3.6
NET_FREQ_3_G22: D9.G22(FREQ[3]_G22) R170.8 SA3.5
NET_MODE_0_D2: D9.D2(MODE[0]_D2) R169.8 SA2.8
NET_MODE_1_D3: D9.D3(MODE[1]_D3) R169.7 SA2.7
NET_MODE_2_C2: D9.C2(MODE[2]_C2) R169.6 SA2.6
NET_MODE_3_B3: D9.B3(MODE[3]_B3) R169.5 SA2.5
NET_NTRST_AD4: D9.AD4(nTRST_AD4) R144.1 XP11.2
NET_OSC_BYP_AB24: D9.AB24(OSC_BYPASS_AB24) G1.1(EN) R180.2 SA4.5
NET_PLLOUT: D9.AC23(PLLOUT_AC23) X14.1
NET_RDLH: D9.AC3(RDLH_LINK_UP_AC3) R162.1
NET_RESET_G23: D9.G23(RESET_G23) R181.2 SB2.1
NET_SMLH: D9.AB4(SMLH_LINK_UP_AB4) R163.1
NET_SPEED_MD_0_Y4: D9.Y4(SPEED_MODE[0]_Y4) R140.1
NET_SPEED_MD_1_AA2: D9.AA2(SPEED_MODE[1]_AA2) R143.1
NET_SPEED_MD_2_AA1: D9.AA1(SPEED_MODE[2]_AA1) R145.1
NET_SPI_NCS_G21: D9.G21(nCE_G21)
NET_SPI_SCK_E21: D9.E21(SCK_E21)
NET_SPI_SI_F22: D9.F22(SI_F22)
NET_SPI_SO_E24: D9.E24(SO_E24)
NET_TCK_Y2: D9.Y2(TCK_Y2) R172.4
NET_TDI_W3: D9.W3(TDI_W3) R172.2
NET_TDO_W4: D9.W4(TDO_W4) R172.1
NET_TMP_DX_N: C120.2 D10.2(DXN) R139.1
NET_TMP_DX_P: C120.1 D10.1(DXP) R138.1
NET_TMS_AC4: D9.AC4(TMS_AC4) R172.3
OSC_XTAL1_IN: BQ2.1 C95.2 SA4.8
OSC_XTAL2_OUT: BQ2.3 C94.2 SA4.7
SCL: D10.7(SCL) R176.1
SDA: D10.6(SDA) R177.1
SW_MDC_1_W1: D9.W1(MDC1_W1) R225.1
SW_MDC_2_Y1: D9.Y1(MDC2_Y1) R226.1
SW_MDIO_1_W2: D9.W2(MDIO1_W2) R111.1
SW_MDIO_2_Y3: D9.Y3(MDIO2_Y3) R227.1
XTAL1_IN: D9.AC22(XTAL1_AC22) SA4.1 SA4.3
XTAL2_OUT: D9.AB22(XTAL2_AB22) SA4.2
NetC202_1: C202.1 C203.1 D9.AB5(PCIE_VPH_AB5) L1.2
NetD9_AA5: D9.AA5(PCIE_RESREF_AA5) R168.1
NetD9_AD10: D9.AD10(RESREF4_AD10) D9.AD16(RESREF3_AD16) D9.J22(RESREF2_J22) D9.T24(RESREF1_T24) R166.1
NetD9_N4: D9.N4(TEST) X13.1
NetD10_3: D10.3(A1) R109.1
NetD10_4: D10.4(A0) R110.1
NetG1_3: G1.3(OUT) R102.2
NetR140_2: R140.2 VD5.1(A)
NetR143_2: R143.2 VD6.1(A)
NetR145_2: R145.2 VD7.1(A)
NetR162_2: R162.2 VD9.1(A)
NetR163_2: R163.2 VD8.1(A)

Not connected (* = marked no-connect by the designer): BQ2 2 4; D9 AA8(NC_AA8)* AA9(NC_AA9)* AA19(NC_AA19)* AB19(NC_AB19)* AC13(NC_AC13)* AD13(NC_AD13)* AD23(NC_AD23)* H23(NC_H23)* K23(NC_K23)* K24(NC_K24)* U21(NC_U21)* U22(NC_U22)*; SB2 2 4(1); X10 2

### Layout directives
differential pair: NET_DX_N, NET_DX_P, NET_TMP_DX_N, NET_TMP_DX_P

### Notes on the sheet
- (near C149) Схема включения 1923КХ028: питание, управляющие сигналы
- (near C155) 1000 пФ
- 10 нФ, 0.1 мкФ
- (near C125) 0.1 мкФ, 1 мкФ
- Дин. ток по VDD_IO < 300 мА
- 10 мкФ
- 3.3V
- Дин. ток по VDD_IO_OSC < 3 мА
- Дин. ток по VPH1-VPH4 < 250 мА
- Дин. ток по PCIE_VPH < 25 мА
- 1000 пФ
- Сумма:                             578 мА
- Мощность:
  .91 Вт
- Дин. ток по VDD_DIG < 1500 мА
- Дин. ток по VP1-VP4 < 250 мА
- Дин. ток по PCIE_VP < 40 мА
- (near C127) 10 нФ
- 1.1V
- Дин. ток по VPT11-VPT14, VPT21-VPT24
- VPT31-VPT34, VPT41-VPT44 < 350 мА
- (near C189) 10 мкФ
- (near C101) 0.1 мкФ, 1 мкФ
- Дин. ток по VDD_PLL < 23 мА
- Дин. ток по PCIE_VPT < 40 мА
- Сумма:                             2203 мА
- Мощность:                    |.43 Вт
- Адрес на SMBus - 1001111 (0x4F)
- OSC_BYPASS = 1 - генератор
- OSC_BYPASS = 0 - резонатор

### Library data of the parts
BQ2 = Quartz_Crystal: GEYER 12.88667
C4-C6 C10 = Cap_1206: GRM31CR60J107ME39L
C94 C95 = Cap_0402: 04025A180JAT2A
C96 C105-C107 C109-C115 C125 C165-C170 C173-C179 C194 C202 C204-C210 C212 C217-C220 C222 C223 C238 = Cap_0402: 0402ZD104KAT2A
C101-C104 C156-C164 C195 C213-C216 = Cap_0402: 0402ZD105KAT2A
C108 C127-C138 C180-C184 C187 = Cap_0402: 04023C103KAT2A
C120 = Cap_0402: 04025A101JAT2A
C139-C148 C150-C155 C193 C196-C201 C203 C211 C224-C226 C228-C237 = Cap_0402: 04025C102KAT2A
C149 C171 C172 C189 = Cap_1206: 12063D106KAT2A
D9 = 1923KX028: as D9 on sheet switch_1923KX028_v_2_sheet_6
D10 = TMP421
G1 = Oscillator: GEYER 12.95000
L1-L3 L5 = L_0805: BLM21PG331SN1
R102 R111 R225-R227 = Res: RC0402FR-0724RL
R109 R110 R144 R176 R177 R180 R181 = Res: CR0402-FX-1102GLF
R138 R139 = Res: RC0402FR-0749R9L
R140 R143 R145 R162 R163 = Res: CR0402-FX-2800GLF
R166 R168 = Res_0402: CR0402-FX-2000GLF
R169 R170 R172 = RES_ARRAY_YC124_YAGEO: YC124-JR-0710KL
SA2-SA4 = dip_switch: dip_switch (4 poles)
SB2 = KEY_BOURNS_7914G_1_000_E: smd key, 5 x 5 mm, h = 1.65 mm
VD5-VD9 = Vd_led: kingbright 2.0 x 1.25mm SMD CHIP LED LAMP
X10 = WF-3: Plug for board, 3 pins, step 2.54mm
X13-X15 = TestPoint: test point

## Sheet switch_1923KX028_v_2_sheet_8.SchDoc
size A3; DocumentNumber: 9; SheetNumber: 9; SheetTotal: 10
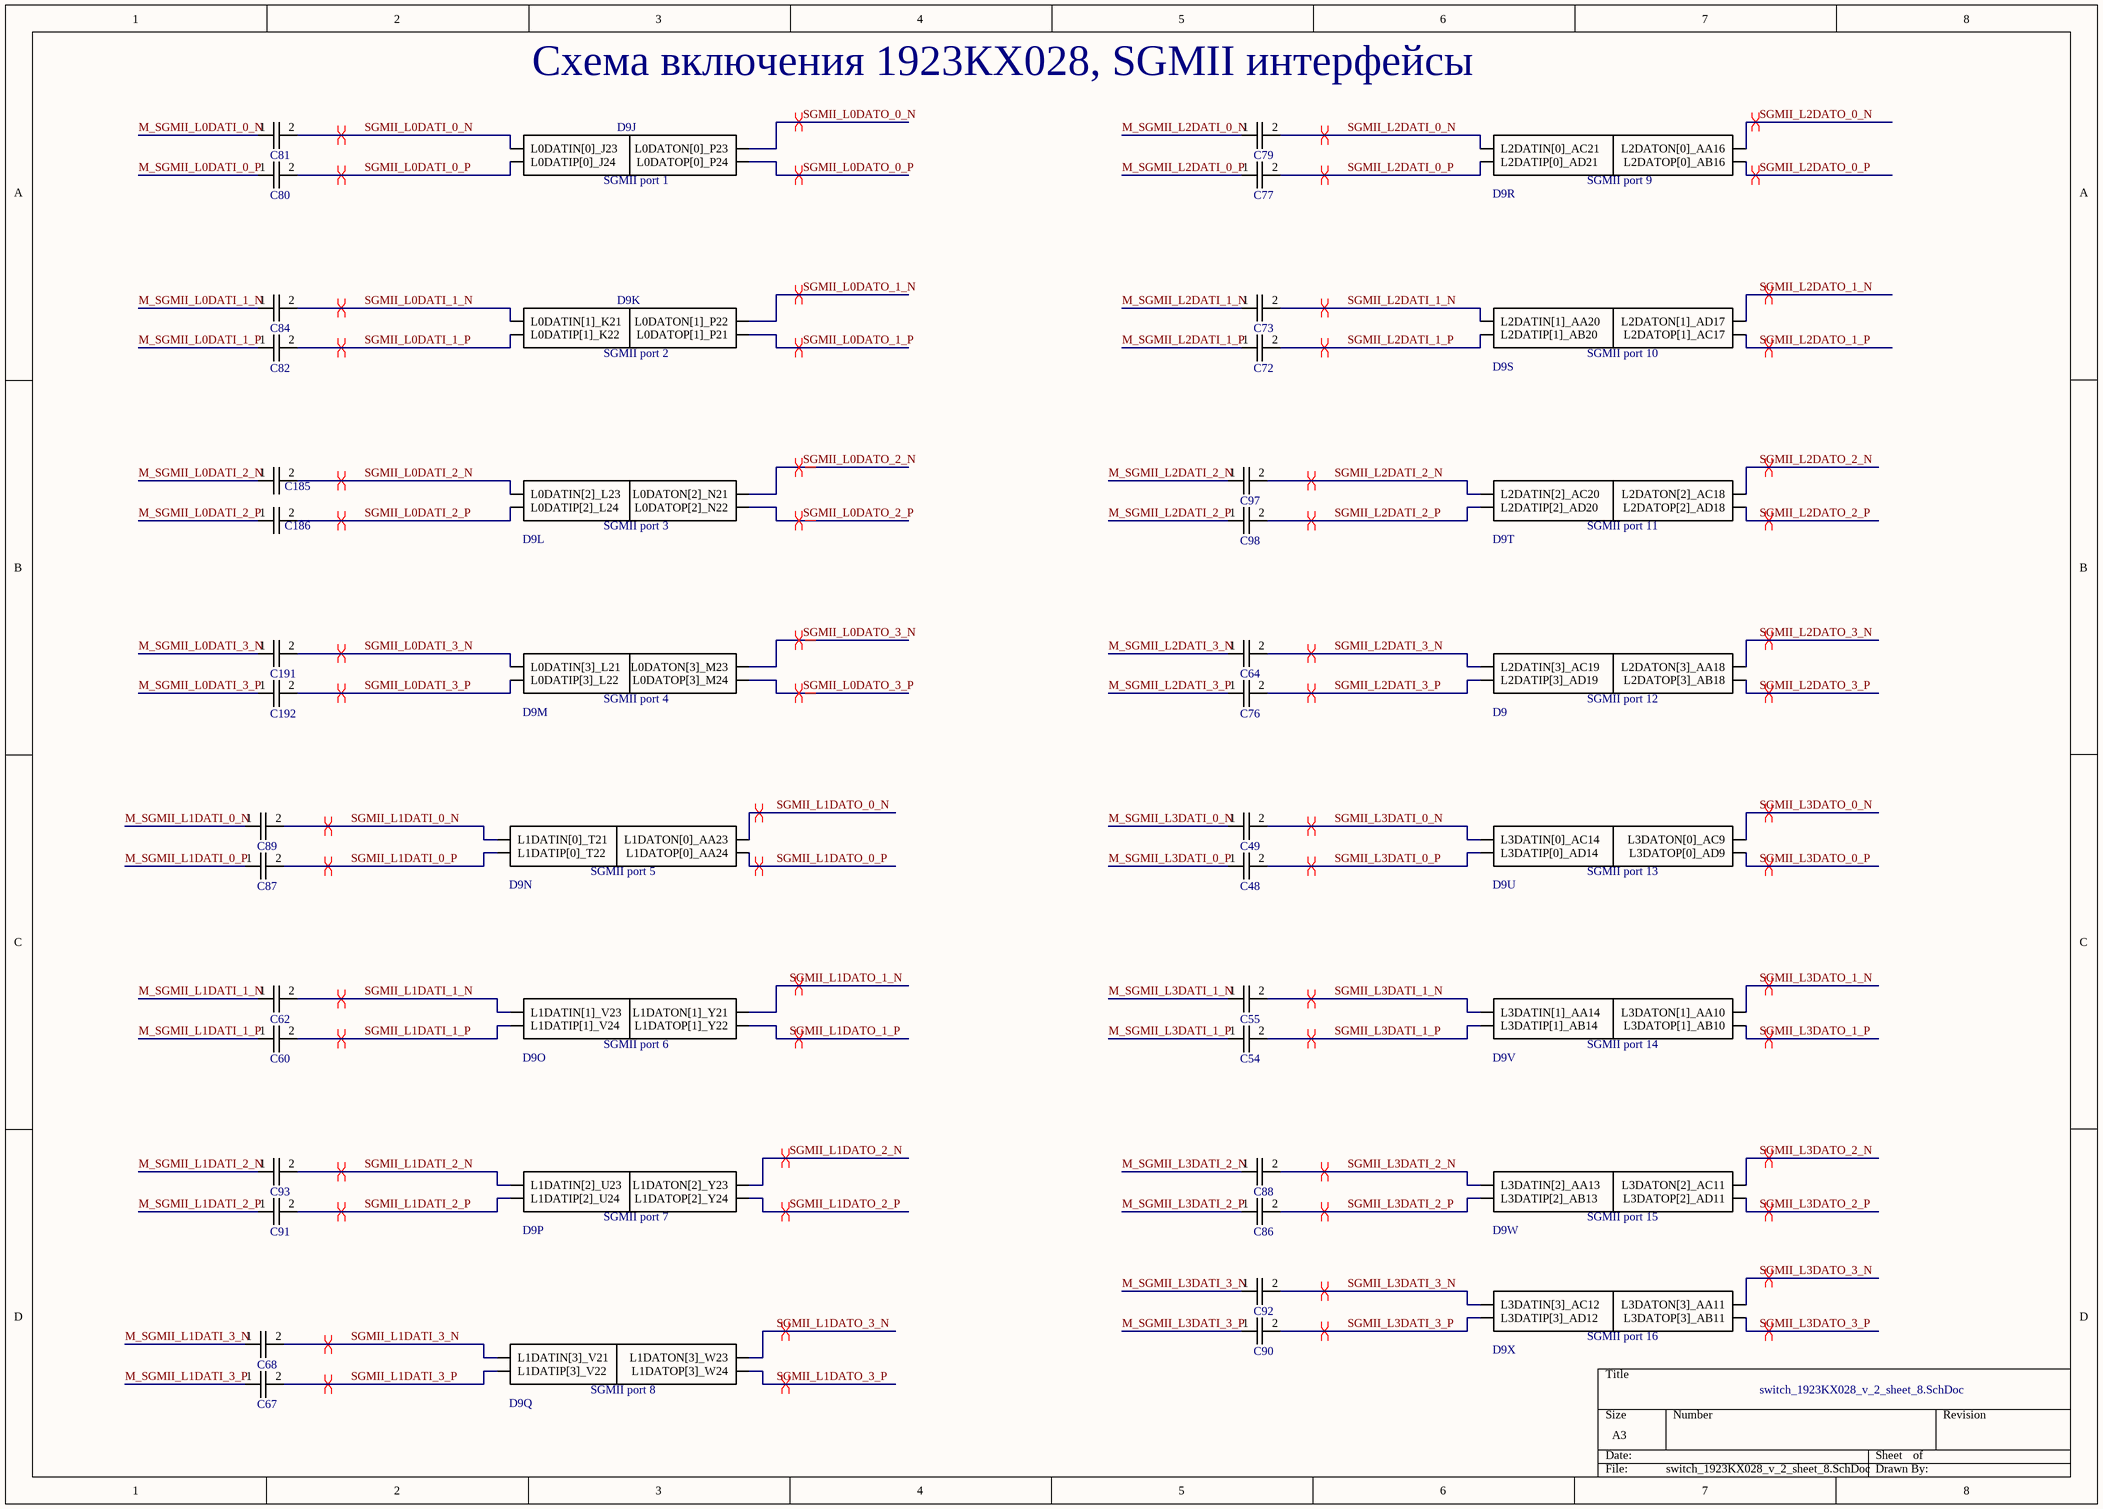
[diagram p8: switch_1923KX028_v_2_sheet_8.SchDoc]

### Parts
C48  100nF, 10V, X5R, 0402  [FOOTPRINT_0402]  (value not drawn)
C49  100nF, 10V, X5R, 0402  [FOOTPRINT_0402]  (value not drawn)
C54  100nF, 10V, X5R, 0402  [FOOTPRINT_0402]  (value not drawn)
C55  100nF, 10V, X5R, 0402  [FOOTPRINT_0402]  (value not drawn)
C60  100nF, 10V, X5R, 0402  [FOOTPRINT_0402]  (value not drawn)
C62  100nF, 10V, X5R, 0402  [FOOTPRINT_0402]  (value not drawn)
C64  100nF, 10V, X5R, 0402  [FOOTPRINT_0402]  (value not drawn)
C67  100nF, 10V, X5R, 0402  [FOOTPRINT_0402]  (value not drawn)
C68  100nF, 10V, X5R, 0402  [FOOTPRINT_0402]  (value not drawn)
C72  100nF, 10V, X5R, 0402  [FOOTPRINT_0402]  (value not drawn)
C73  100nF, 10V, X5R, 0402  [FOOTPRINT_0402]  (value not drawn)
C76  100nF, 10V, X5R, 0402  [FOOTPRINT_0402]  (value not drawn)
C77  100nF, 10V, X5R, 0402  [FOOTPRINT_0402]  (value not drawn)
C79  100nF, 10V, X5R, 0402  [FOOTPRINT_0402]  (value not drawn)
C80  100nF, 10V, X5R, 0402  [FOOTPRINT_0402]  (value not drawn)
C81  100nF, 10V, X5R, 0402  [FOOTPRINT_0402]  (value not drawn)
C82  100nF, 10V, X5R, 0402  [FOOTPRINT_0402]  (value not drawn)
C84  100nF, 10V, X5R, 0402  [FOOTPRINT_0402]  (value not drawn)
C86  100nF, 10V, X5R, 0402  [FOOTPRINT_0402]  (value not drawn)
C87  100nF, 10V, X5R, 0402  [FOOTPRINT_0402]  (value not drawn)
C88  100nF, 10V, X5R, 0402  [FOOTPRINT_0402]  (value not drawn)
C89  100nF, 10V, X5R, 0402  [FOOTPRINT_0402]  (value not drawn)
C90  100nF, 10V, X5R, 0402  [FOOTPRINT_0402]  (value not drawn)
C91  100nF, 10V, X5R, 0402  [FOOTPRINT_0402]  (value not drawn)
C92  100nF, 10V, X5R, 0402  [FOOTPRINT_0402]  (value not drawn)
C93  100nF, 10V, X5R, 0402  [FOOTPRINT_0402]  (value not drawn)
C97  100nF, 10V, X5R, 0402  [FOOTPRINT_0402]  (value not drawn)
C98  100nF, 10V, X5R, 0402  [FOOTPRINT_0402]  (value not drawn)
C185  100nF, 10V, X5R, 0402  [FOOTPRINT_0402]  (value not drawn)
C186  100nF, 10V, X5R, 0402  [FOOTPRINT_0402]  (value not drawn)
C191  100nF, 10V, X5R, 0402  [FOOTPRINT_0402]  (value not drawn)
C192  100nF, 10V, X5R, 0402  [FOOTPRINT_0402]  (value not drawn)
D9  1923KX028  [FOOTPRINT_MK8303.576-1]  (value not drawn)  (parts J,K,L,M,N,O,P,Q,R,S,T,U,V,W,X,27 of 27)

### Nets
M_SGMII_L0DATI_0_N: C81.1
M_SGMII_L0DATI_0_P: C80.1
M_SGMII_L0DATI_1_N: C84.1
M_SGMII_L0DATI_1_P: C82.1
M_SGMII_L0DATI_2_N: C185.1
M_SGMII_L0DATI_2_P: C186.1
M_SGMII_L0DATI_3_N: C191.1
M_SGMII_L0DATI_3_P: C192.1
M_SGMII_L1DATI_0_N: C89.1
M_SGMII_L1DATI_0_P: C87.1
M_SGMII_L1DATI_1_N: C62.1
M_SGMII_L1DATI_1_P: C60.1
M_SGMII_L1DATI_2_N: C93.1
M_SGMII_L1DATI_2_P: C91.1
M_SGMII_L1DATI_3_N: C68.1
M_SGMII_L1DATI_3_P: C67.1
M_SGMII_L2DATI_0_N: C79.1
M_SGMII_L2DATI_0_P: C77.1
M_SGMII_L2DATI_1_N: C73.1
M_SGMII_L2DATI_1_P: C72.1
M_SGMII_L2DATI_2_N: C97.1
M_SGMII_L2DATI_2_P: C98.1
M_SGMII_L2DATI_3_N: C64.1
M_SGMII_L2DATI_3_P: C76.1
M_SGMII_L3DATI_0_N: C49.1
M_SGMII_L3DATI_0_P: C48.1
M_SGMII_L3DATI_1_N: C55.1
M_SGMII_L3DATI_1_P: C54.1
M_SGMII_L3DATI_2_N: C88.1
M_SGMII_L3DATI_2_P: C86.1
M_SGMII_L3DATI_3_N: C92.1
M_SGMII_L3DATI_3_P: C90.1
SGMII_L0DATI_0_N: C81.2 D9.J23(L0DATIN[0]_J23)
SGMII_L0DATI_0_P: C80.2 D9.J24(L0DATIP[0]_J24)
SGMII_L0DATI_1_N: C84.2 D9.K21(L0DATIN[1]_K21)
SGMII_L0DATI_1_P: C82.2 D9.K22(L0DATIP[1]_K22)
SGMII_L0DATI_2_N: C185.2 D9.L23(L0DATIN[2]_L23)
SGMII_L0DATI_2_P: C186.2 D9.L24(L0DATIP[2]_L24)
SGMII_L0DATI_3_N: C191.2 D9.L21(L0DATIN[3]_L21)
SGMII_L0DATI_3_P: C192.2 D9.L22(L0DATIP[3]_L22)
SGMII_L0DATO_0_N: D9.P23(L0DATON[0]_P23)
SGMII_L0DATO_0_P: D9.P24(L0DATOP[0]_P24)
SGMII_L0DATO_1_N: D9.P22(L0DATON[1]_P22)
SGMII_L0DATO_1_P: D9.P21(L0DATOP[1]_P21)
SGMII_L0DATO_2_N: D9.N21(L0DATON[2]_N21)
SGMII_L0DATO_2_P: D9.N22(L0DATOP[2]_N22)
SGMII_L0DATO_3_N: D9.M23(L0DATON[3]_M23)
SGMII_L0DATO_3_P: D9.M24(L0DATOP[3]_M24)
SGMII_L1DATI_0_N: C89.2 D9.T21(L1DATIN[0]_T21)
SGMII_L1DATI_0_P: C87.2 D9.T22(L1DATIP[0]_T22)
SGMII_L1DATI_1_N: C62.2 D9.V23(L1DATIN[1]_V23)
SGMII_L1DATI_1_P: C60.2 D9.V24(L1DATIP[1]_V24)
SGMII_L1DATI_2_N: C93.2 D9.U23(L1DATIN[2]_U23)
SGMII_L1DATI_2_P: C91.2 D9.U24(L1DATIP[2]_U24)
SGMII_L1DATI_3_N: C68.2 D9.V21(L1DATIN[3]_V21)
SGMII_L1DATI_3_P: C67.2 D9.V22(L1DATIP[3]_V22)
SGMII_L1DATO_0_N: D9.AA23(L1DATON[0]_AA23)
SGMII_L1DATO_0_P: D9.AA24(L1DATOP[0]_AA24)
SGMII_L1DATO_1_N: D9.Y21(L1DATON[1]_Y21)
SGMII_L1DATO_1_P: D9.Y22(L1DATOP[1]_Y22)
SGMII_L1DATO_2_N: D9.Y23(L1DATON[2]_Y23)
SGMII_L1DATO_2_P: D9.Y24(L1DATOP[2]_Y24)
SGMII_L1DATO_3_N: D9.W23(L1DATON[3]_W23)
SGMII_L1DATO_3_P: D9.W24(L1DATOP[3]_W24)
SGMII_L2DATI_0_N: C79.2 D9.AC21(L2DATIN[0]_AC21)
SGMII_L2DATI_0_P: C77.2 D9.AD21(L2DATIP[0]_AD21)
SGMII_L2DATI_1_N: C73.2 D9.AA20(L2DATIN[1]_AA20)
SGMII_L2DATI_1_P: C72.2 D9.AB20(L2DATIP[1]_AB20)
SGMII_L2DATI_2_N: C97.2 D9.AC20(L2DATIN[2]_AC20)
SGMII_L2DATI_2_P: C98.2 D9.AD20(L2DATIP[2]_AD20)
SGMII_L2DATI_3_N: C64.2 D9.AC19(L2DATIN[3]_AC19)
SGMII_L2DATI_3_P: C76.2 D9.AD19(L2DATIP[3]_AD19)
SGMII_L2DATO_0_N: D9.AA16(L2DATON[0]_AA16)
SGMII_L2DATO_0_P: D9.AB16(L2DATOP[0]_AB16)
SGMII_L2DATO_1_N: D9.AD17(L2DATON[1]_AD17)
SGMII_L2DATO_1_P: D9.AC17(L2DATOP[1]_AC17)
SGMII_L2DATO_2_N: D9.AC18(L2DATON[2]_AC18)
SGMII_L2DATO_2_P: D9.AD18(L2DATOP[2]_AD18)
SGMII_L2DATO_3_N: D9.AA18(L2DATON[3]_AA18)
SGMII_L2DATO_3_P: D9.AB18(L2DATOP[3]_AB18)
SGMII_L3DATI_0_N: C49.2 D9.AC14(L3DATIN[0]_AC14)
SGMII_L3DATI_0_P: C48.2 D9.AD14(L3DATIP[0]_AD14)
SGMII_L3DATI_1_N: C55.2 D9.AA14(L3DATIN[1]_AA14)
SGMII_L3DATI_1_P: C54.2 D9.AB14(L3DATIP[1]_AB14)
SGMII_L3DATI_2_N: C88.2 D9.AA13(L3DATIN[2]_AA13)
SGMII_L3DATI_2_P: C86.2 D9.AB13(L3DATIP[2]_AB13)
SGMII_L3DATI_3_N: C92.2 D9.AC12(L3DATIN[3]_AC12)
SGMII_L3DATI_3_P: C90.2 D9.AD12(L3DATIP[3]_AD12)
SGMII_L3DATO_0_N: D9.AC9(L3DATON[0]_AC9)
SGMII_L3DATO_0_P: D9.AD9(L3DATOP[0]_AD9)
SGMII_L3DATO_1_N: D9.AA10(L3DATON[1]_AA10)
SGMII_L3DATO_1_P: D9.AB10(L3DATOP[1]_AB10)
SGMII_L3DATO_2_N: D9.AC11(L3DATON[2]_AC11)
SGMII_L3DATO_2_P: D9.AD11(L3DATOP[2]_AD11)
SGMII_L3DATO_3_N: D9.AA11(L3DATON[3]_AA11)
SGMII_L3DATO_3_P: D9.AB11(L3DATOP[3]_AB11)

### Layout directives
differential pair: SGMII_L0DATI_0_N, SGMII_L0DATI_0_P, SGMII_L0DATI_1_N, SGMII_L0DATI_1_P, SGMII_L0DATI_2_N, SGMII_L0DATI_2_P, SGMII_L0DATI_3_N, SGMII_L0DATI_3_P, SGMII_L0DATO_0_N, SGMII_L0DATO_0_P, SGMII_L0DATO_1_N, SGMII_L0DATO_1_P, SGMII_L0DATO_2_N, SGMII_L0DATO_2_P, SGMII_L0DATO_3_N, SGMII_L0DATO_3_P, SGMII_L1DATI_0_N, SGMII_L1DATI_0_P, SGMII_L1DATI_1_N, SGMII_L1DATI_1_P, SGMII_L1DATI_2_N, SGMII_L1DATI_2_P, SGMII_L1DATI_3_N, SGMII_L1DATI_3_P, SGMII_L1DATO_0_N, SGMII_L1DATO_0_P, SGMII_L1DATO_1_N, SGMII_L1DATO_1_P, SGMII_L1DATO_2_N, SGMII_L1DATO_2_P, SGMII_L1DATO_3_N, SGMII_L1DATO_3_P, SGMII_L2DATI_0_N, SGMII_L2DATI_0_P, SGMII_L2DATI_1_N, SGMII_L2DATI_1_P, SGMII_L2DATI_2_N, SGMII_L2DATI_2_P, SGMII_L2DATI_3_N, SGMII_L2DATI_3_P, SGMII_L2DATO_0_N, SGMII_L2DATO_0_P, SGMII_L2DATO_1_N, SGMII_L2DATO_1_P, SGMII_L2DATO_2_N, SGMII_L2DATO_2_P, SGMII_L2DATO_3_N, SGMII_L2DATO_3_P, SGMII_L3DATI_0_N, SGMII_L3DATI_0_P, SGMII_L3DATI_1_N, SGMII_L3DATI_1_P, SGMII_L3DATI_2_N, SGMII_L3DATI_2_P, SGMII_L3DATI_3_N, SGMII_L3DATI_3_P, SGMII_L3DATO_0_N, SGMII_L3DATO_0_P, SGMII_L3DATO_1_N, SGMII_L3DATO_1_P, SGMII_L3DATO_2_N, SGMII_L3DATO_2_P, SGMII_L3DATO_3_N, SGMII_L3DATO_3_P

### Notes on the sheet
- Схема включения 1923КХ028, SGMII интерфейсы

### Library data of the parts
C48 C49 C54 C55 C60 C62 C64 C67 C68 C72 C73 C76 C77 C79-C82 C84 C86-C93 C97 C98 C185 C186 C191 C192 = Cap_0402: 0402ZD104KAT2A
D9 = 1923KX028: as D9 on sheet switch_1923KX028_v_2_sheet_6

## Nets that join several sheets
+1.1V: switch_1923KX028_v_2_sheet_1 (17 pins), switch_1923KX028_v_2_sheet_2 (45 pins), switch_1923KX028_v_2_sheet_3 (45 pins), switch_1923KX028_v_2_sheet_4 (30 pins), switch_1923KX028_v_2_sheet_7 (143 pins)
+3.3V: switch_1923KX028_v_2_sheet_1 (22 pins), switch_1923KX028_v_2_sheet_2 (76 pins), switch_1923KX028_v_2_sheet_3 (64 pins), switch_1923KX028_v_2_sheet_4 (66 pins), switch_1923KX028_v_2_sheet_5 (43 pins), switch_1923KX028_v_2_sheet_7 (110 pins)
GND: switch_1923KX028_v_2_sheet_1 (67 pins), switch_1923KX028_v_2_sheet_2 (131 pins), switch_1923KX028_v_2_sheet_3 (129 pins), switch_1923KX028_v_2_sheet_4 (110 pins), switch_1923KX028_v_2_sheet_5 (101 pins), switch_1923KX028_v_2_sheet_6 (70 pins), switch_1923KX028_v_2_sheet_7 (303 pins)
InputPWR: switch_1923KX028_v_2_sheet_1 (20 pins), switch_1923KX028_v_2_sheet_7 (X10.1)
M_SGMII_L0DATI_0_N: switch_1923KX028_v_2_sheet_2 (X1.57), switch_1923KX028_v_2_sheet_8 (C81.1)
M_SGMII_L0DATI_0_P: switch_1923KX028_v_2_sheet_2 (X1.59), switch_1923KX028_v_2_sheet_8 (C80.1)
M_SGMII_L0DATI_1_N: switch_1923KX028_v_2_sheet_4 (X8.117), switch_1923KX028_v_2_sheet_8 (C84.1)
M_SGMII_L0DATI_1_P: switch_1923KX028_v_2_sheet_4 (X8.119), switch_1923KX028_v_2_sheet_8 (C82.1)
M_SGMII_L0DATI_2_N: switch_1923KX028_v_2_sheet_2 (X1.117), switch_1923KX028_v_2_sheet_8 (C185.1)
M_SGMII_L0DATI_2_P: switch_1923KX028_v_2_sheet_2 (X1.119), switch_1923KX028_v_2_sheet_8 (C186.1)
M_SGMII_L0DATI_3_N: switch_1923KX028_v_2_sheet_4 (X8.57), switch_1923KX028_v_2_sheet_8 (C191.1)
M_SGMII_L0DATI_3_P: switch_1923KX028_v_2_sheet_4 (X8.59), switch_1923KX028_v_2_sheet_8 (C192.1)
M_SGMII_L1DATI_0_N: switch_1923KX028_v_2_sheet_2 (R17.2 R21.1 X2.57), switch_1923KX028_v_2_sheet_8 (C89.1)
M_SGMII_L1DATI_0_P: switch_1923KX028_v_2_sheet_2 (R18.2 R22.1 X2.59), switch_1923KX028_v_2_sheet_8 (C87.1)
M_SGMII_L1DATI_1_N: switch_1923KX028_v_2_sheet_2 (R60.2 R64.1 X3.117), switch_1923KX028_v_2_sheet_8 (C62.1)
M_SGMII_L1DATI_1_P: switch_1923KX028_v_2_sheet_2 (R61.2 R65.1 X3.119), switch_1923KX028_v_2_sheet_8 (C60.1)
M_SGMII_L1DATI_2_N: switch_1923KX028_v_2_sheet_2 (R51.2 R62.1 X2.117), switch_1923KX028_v_2_sheet_8 (C93.1)
M_SGMII_L1DATI_2_P: switch_1923KX028_v_2_sheet_2 (R59.2 R63.1 X2.119), switch_1923KX028_v_2_sheet_8 (C91.1)
M_SGMII_L1DATI_3_N: switch_1923KX028_v_2_sheet_2 (R19.2 R23.1 X3.57), switch_1923KX028_v_2_sheet_8 (C68.1)
M_SGMII_L1DATI_3_P: switch_1923KX028_v_2_sheet_2 (R20.2 R24.1 X3.59), switch_1923KX028_v_2_sheet_8 (C67.1)
M_SGMII_L2DATI_0_N: switch_1923KX028_v_2_sheet_3 (X4.57), switch_1923KX028_v_2_sheet_8 (C79.1)
M_SGMII_L2DATI_0_P: switch_1923KX028_v_2_sheet_3 (X4.59), switch_1923KX028_v_2_sheet_8 (C77.1)
M_SGMII_L2DATI_1_N: switch_1923KX028_v_2_sheet_3 (X5.117), switch_1923KX028_v_2_sheet_8 (C73.1)
M_SGMII_L2DATI_1_P: switch_1923KX028_v_2_sheet_3 (X5.119), switch_1923KX028_v_2_sheet_8 (C72.1)
M_SGMII_L2DATI_2_N: switch_1923KX028_v_2_sheet_3 (X4.117), switch_1923KX028_v_2_sheet_8 (C97.1)
M_SGMII_L2DATI_2_P: switch_1923KX028_v_2_sheet_3 (X4.119), switch_1923KX028_v_2_sheet_8 (C98.1)
M_SGMII_L2DATI_3_N: switch_1923KX028_v_2_sheet_3 (X5.57), switch_1923KX028_v_2_sheet_8 (C64.1)
M_SGMII_L2DATI_3_P: switch_1923KX028_v_2_sheet_3 (X5.59), switch_1923KX028_v_2_sheet_8 (C76.1)
M_SGMII_L3DATI_0_N: switch_1923KX028_v_2_sheet_3 (R68.2 R70.1 X6.57), switch_1923KX028_v_2_sheet_8 (C49.1)
M_SGMII_L3DATI_0_P: switch_1923KX028_v_2_sheet_3 (R69.2 R71.1 X6.59), switch_1923KX028_v_2_sheet_8 (C48.1)
M_SGMII_L3DATI_1_N: switch_1923KX028_v_2_sheet_4 (R112.2 R114.1 X7.117), switch_1923KX028_v_2_sheet_8 (C55.1)
M_SGMII_L3DATI_1_P: switch_1923KX028_v_2_sheet_4 (R113.2 R115.1 X7.119), switch_1923KX028_v_2_sheet_8 (C54.1)
M_SGMII_L3DATI_2_N: switch_1923KX028_v_2_sheet_3 (R84.2 R86.1 X6.117), switch_1923KX028_v_2_sheet_8 (C88.1)
M_SGMII_L3DATI_2_P: switch_1923KX028_v_2_sheet_3 (R85.2 R87.1 X6.119), switch_1923KX028_v_2_sheet_8 (C86.1)
M_SGMII_L3DATI_3_N: switch_1923KX028_v_2_sheet_4 (R92.2 R96.1 X7.57), switch_1923KX028_v_2_sheet_8 (C92.1)
M_SGMII_L3DATI_3_P: switch_1923KX028_v_2_sheet_4 (R93.2 R97.1 X7.59), switch_1923KX028_v_2_sheet_8 (C90.1)
MDC_1: switch_1923KX028_v_2_sheet_4 (9 pins), switch_1923KX028_v_2_sheet_5 (D11.30 D11.35), switch_1923KX028_v_2_sheet_7 (R225.2)
MDC_2: switch_1923KX028_v_2_sheet_4 (9 pins), switch_1923KX028_v_2_sheet_7 (R226.2)
MDIO_1: switch_1923KX028_v_2_sheet_2 (6 pins), switch_1923KX028_v_2_sheet_4 (R100.2 X8.39 X8.99), switch_1923KX028_v_2_sheet_5 (D11.33 D11.36), switch_1923KX028_v_2_sheet_7 (R111.2)
MDIO_2: switch_1923KX028_v_2_sheet_3 (6 pins), switch_1923KX028_v_2_sheet_4 (R104.2 X7.39 X7.99), switch_1923KX028_v_2_sheet_7 (R227.2)
NET_MODE_0_D2: switch_1923KX028_v_2_sheet_5 (D11.63), switch_1923KX028_v_2_sheet_7 (D9.D2 R169.8 SA2.8)
NET_MODE_1_D3: switch_1923KX028_v_2_sheet_5 (D11.62), switch_1923KX028_v_2_sheet_7 (D9.D3 R169.7 SA2.7)
NET_MODE_2_C2: switch_1923KX028_v_2_sheet_5 (D11.61), switch_1923KX028_v_2_sheet_7 (D9.C2 R169.6 SA2.6)
NET_MODE_3_B3: switch_1923KX028_v_2_sheet_5 (D11.60), switch_1923KX028_v_2_sheet_7 (D9.B3 R169.5 SA2.5)
NET_RESET_G23: switch_1923KX028_v_2_sheet_5 (XP2.2 XP6.1 XP7.1), switch_1923KX028_v_2_sheet_7 (D9.G23 R181.2 SB2.1)
NET_SPI_NCS_G21: switch_1923KX028_v_2_sheet_5 (R161.1 SA5.3 SA6.3), switch_1923KX028_v_2_sheet_7 (D9.G21)
NET_SPI_SCK_E21: switch_1923KX028_v_2_sheet_5 (R167.1 SA5.2 SA6.2), switch_1923KX028_v_2_sheet_7 (D9.E21)
NET_SPI_SI_F22: switch_1923KX028_v_2_sheet_5 (R164.1 SA5.1 SA6.1), switch_1923KX028_v_2_sheet_7 (D9.F22)
NET_SPI_SO_E24: switch_1923KX028_v_2_sheet_5 (R165.1 SA5.4 SA6.4), switch_1923KX028_v_2_sheet_7 (D9.E24)
NET_TCK_Y2: switch_1923KX028_v_2_sheet_5 (D11.22), switch_1923KX028_v_2_sheet_7 (D9.Y2 R172.4)
NET_TDI_W3: switch_1923KX028_v_2_sheet_5 (D11.26), switch_1923KX028_v_2_sheet_7 (D9.W3 R172.2)
NET_TDO_W4: switch_1923KX028_v_2_sheet_5 (D11.25), switch_1923KX028_v_2_sheet_7 (D9.W4 R172.1)
NET_TMS_AC4: switch_1923KX028_v_2_sheet_5 (D11.21), switch_1923KX028_v_2_sheet_7 (D9.AC4 R172.3)
PHY_1_RST#: switch_1923KX028_v_2_sheet_2 (X1.1), switch_1923KX028_v_2_sheet_5 (D14.15)
PHY_2_RST#: switch_1923KX028_v_2_sheet_4 (X8.61), switch_1923KX028_v_2_sheet_5 (D14.1)
PHY_3_RST#: switch_1923KX028_v_2_sheet_2 (X1.61), switch_1923KX028_v_2_sheet_5 (D14.2)
PHY_4_RST#: switch_1923KX028_v_2_sheet_4 (X8.1), switch_1923KX028_v_2_sheet_5 (D14.3)
PHY_5_RST#: switch_1923KX028_v_2_sheet_2 (X2.1), switch_1923KX028_v_2_sheet_5 (D14.4)
PHY_6_RST#: switch_1923KX028_v_2_sheet_2 (X3.61), switch_1923KX028_v_2_sheet_5 (D14.5)
PHY_7_RST#: switch_1923KX028_v_2_sheet_2 (X2.61), switch_1923KX028_v_2_sheet_5 (D14.6)
PHY_8_RST#: switch_1923KX028_v_2_sheet_2 (X3.1), switch_1923KX028_v_2_sheet_5 (D14.7)
PHY_9_RST#: switch_1923KX028_v_2_sheet_3 (X4.1), switch_1923KX028_v_2_sheet_5 (D15.15)
PHY_10_RST#: switch_1923KX028_v_2_sheet_3 (X5.61), switch_1923KX028_v_2_sheet_5 (D15.7)
PHY_11_RST#: switch_1923KX028_v_2_sheet_3 (X4.61), switch_1923KX028_v_2_sheet_5 (D15.6)
PHY_12_RST#: switch_1923KX028_v_2_sheet_3 (X5.1), switch_1923KX028_v_2_sheet_5 (D15.5)
PHY_13_RST#: switch_1923KX028_v_2_sheet_3 (X6.1), switch_1923KX028_v_2_sheet_5 (D15.4)
PHY_14_RST#: switch_1923KX028_v_2_sheet_4 (X7.61), switch_1923KX028_v_2_sheet_5 (D15.3)
PHY_15_RST#: switch_1923KX028_v_2_sheet_3 (X6.61), switch_1923KX028_v_2_sheet_5 (D15.2)
PHY_16_RST#: switch_1923KX028_v_2_sheet_4 (X7.1), switch_1923KX028_v_2_sheet_5 (D15.1)
SCL: switch_1923KX028_v_2_sheet_5 (D11.42 D16.14), switch_1923KX028_v_2_sheet_7 (D10.7 R176.1)
SDA: switch_1923KX028_v_2_sheet_5 (D11.41 D16.15), switch_1923KX028_v_2_sheet_7 (D10.6 R177.1)
SGMII_L0DATO_0_N: switch_1923KX028_v_2_sheet_2 (X1.58), switch_1923KX028_v_2_sheet_8 (D9.P23)
SGMII_L0DATO_0_P: switch_1923KX028_v_2_sheet_2 (X1.60), switch_1923KX028_v_2_sheet_8 (D9.P24)
SGMII_L0DATO_1_N: switch_1923KX028_v_2_sheet_4 (X8.118), switch_1923KX028_v_2_sheet_8 (D9.P22)
SGMII_L0DATO_1_P: switch_1923KX028_v_2_sheet_4 (X8.120), switch_1923KX028_v_2_sheet_8 (D9.P21)
SGMII_L0DATO_2_N: switch_1923KX028_v_2_sheet_2 (X1.118), switch_1923KX028_v_2_sheet_8 (D9.N21)
SGMII_L0DATO_2_P: switch_1923KX028_v_2_sheet_2 (X1.120), switch_1923KX028_v_2_sheet_8 (D9.N22)
SGMII_L0DATO_3_N: switch_1923KX028_v_2_sheet_4 (X8.58), switch_1923KX028_v_2_sheet_8 (D9.M23)
SGMII_L0DATO_3_P: switch_1923KX028_v_2_sheet_4 (X8.60), switch_1923KX028_v_2_sheet_8 (D9.M24)
SGMII_L1DATO_0_N: switch_1923KX028_v_2_sheet_2 (X2.58), switch_1923KX028_v_2_sheet_8 (D9.AA23)
SGMII_L1DATO_0_P: switch_1923KX028_v_2_sheet_2 (X2.60), switch_1923KX028_v_2_sheet_8 (D9.AA24)
SGMII_L1DATO_1_N: switch_1923KX028_v_2_sheet_2 (X3.118), switch_1923KX028_v_2_sheet_8 (D9.Y21)
SGMII_L1DATO_1_P: switch_1923KX028_v_2_sheet_2 (X3.120), switch_1923KX028_v_2_sheet_8 (D9.Y22)
SGMII_L1DATO_2_N: switch_1923KX028_v_2_sheet_2 (X2.118), switch_1923KX028_v_2_sheet_8 (D9.Y23)
SGMII_L1DATO_2_P: switch_1923KX028_v_2_sheet_2 (X2.120), switch_1923KX028_v_2_sheet_8 (D9.Y24)
SGMII_L1DATO_3_N: switch_1923KX028_v_2_sheet_2 (X3.58), switch_1923KX028_v_2_sheet_8 (D9.W23)
SGMII_L1DATO_3_P: switch_1923KX028_v_2_sheet_2 (X3.60), switch_1923KX028_v_2_sheet_8 (D9.W24)
SGMII_L2DATO_0_N: switch_1923KX028_v_2_sheet_3 (X4.58), switch_1923KX028_v_2_sheet_8 (D9.AA16)
SGMII_L2DATO_0_P: switch_1923KX028_v_2_sheet_3 (X4.60), switch_1923KX028_v_2_sheet_8 (D9.AB16)
SGMII_L2DATO_1_N: switch_1923KX028_v_2_sheet_3 (X5.118), switch_1923KX028_v_2_sheet_8 (D9.AD17)
SGMII_L2DATO_1_P: switch_1923KX028_v_2_sheet_3 (X5.120), switch_1923KX028_v_2_sheet_8 (D9.AC17)
SGMII_L2DATO_2_N: switch_1923KX028_v_2_sheet_3 (X4.118), switch_1923KX028_v_2_sheet_8 (D9.AC18)
SGMII_L2DATO_2_P: switch_1923KX028_v_2_sheet_3 (X4.120), switch_1923KX028_v_2_sheet_8 (D9.AD18)
SGMII_L2DATO_3_N: switch_1923KX028_v_2_sheet_3 (X5.58), switch_1923KX028_v_2_sheet_8 (D9.AA18)
SGMII_L2DATO_3_P: switch_1923KX028_v_2_sheet_3 (X5.60), switch_1923KX028_v_2_sheet_8 (D9.AB18)
SGMII_L3DATO_0_N: switch_1923KX028_v_2_sheet_3 (X6.58), switch_1923KX028_v_2_sheet_8 (D9.AC9)
SGMII_L3DATO_0_P: switch_1923KX028_v_2_sheet_3 (X6.60), switch_1923KX028_v_2_sheet_8 (D9.AD9)
SGMII_L3DATO_1_N: switch_1923KX028_v_2_sheet_4 (X7.118), switch_1923KX028_v_2_sheet_8 (D9.AA10)
SGMII_L3DATO_1_P: switch_1923KX028_v_2_sheet_4 (X7.120), switch_1923KX028_v_2_sheet_8 (D9.AB10)
SGMII_L3DATO_2_N: switch_1923KX028_v_2_sheet_3 (X6.118), switch_1923KX028_v_2_sheet_8 (D9.AC11)
SGMII_L3DATO_2_P: switch_1923KX028_v_2_sheet_3 (X6.120), switch_1923KX028_v_2_sheet_8 (D9.AD11)
SGMII_L3DATO_3_N: switch_1923KX028_v_2_sheet_4 (X7.58), switch_1923KX028_v_2_sheet_8 (D9.AA11)
SGMII_L3DATO_3_P: switch_1923KX028_v_2_sheet_4 (X7.60), switch_1923KX028_v_2_sheet_8 (D9.AB11)
X1_1_I2C_SCL: switch_1923KX028_v_2_sheet_2 (R15.2 X1.29), switch_1923KX028_v_2_sheet_5 (D16.5)
X1_1_I2C_SDA: switch_1923KX028_v_2_sheet_2 (R182.2 X1.31), switch_1923KX028_v_2_sheet_5 (D16.4)
X1_1_MDC_1: switch_1923KX028_v_2_sheet_2 (X1.40), switch_1923KX028_v_2_sheet_4 (D5.8)
X1_1_SFP_PRES: switch_1923KX028_v_2_sheet_2 (R13.2 X1.35), switch_1923KX028_v_2_sheet_5 (D11.59)
X1_2_I2C_SCL: switch_1923KX028_v_2_sheet_2 (R184.2 X1.89), switch_1923KX028_v_2_sheet_5 (D16.10)
X1_2_I2C_SDA: switch_1923KX028_v_2_sheet_2 (R185.2 X1.91), switch_1923KX028_v_2_sheet_5 (D16.9)
X1_2_MDC_1: switch_1923KX028_v_2_sheet_2 (X1.100), switch_1923KX028_v_2_sheet_4 (D5.11)
X1_2_SFP_PRES: switch_1923KX028_v_2_sheet_2 (R183.2 X1.95), switch_1923KX028_v_2_sheet_5 (D11.58)
X2_1_MDC_1: switch_1923KX028_v_2_sheet_2 (X2.40), switch_1923KX028_v_2_sheet_4 (D6.3)
X2_2_MDC_1: switch_1923KX028_v_2_sheet_2 (X2.100), switch_1923KX028_v_2_sheet_4 (D6.6)
X3_1_MDC_1: switch_1923KX028_v_2_sheet_2 (X3.40), switch_1923KX028_v_2_sheet_4 (D6.8)
X3_2_MDC_1: switch_1923KX028_v_2_sheet_2 (X3.100), switch_1923KX028_v_2_sheet_4 (D6.11)
X4_1_MDC_2: switch_1923KX028_v_2_sheet_3 (X4.40), switch_1923KX028_v_2_sheet_4 (D7.3)
X4_2_MDC_2: switch_1923KX028_v_2_sheet_3 (X4.100), switch_1923KX028_v_2_sheet_4 (D7.6)
X5_1_MDC_2: switch_1923KX028_v_2_sheet_3 (X5.40), switch_1923KX028_v_2_sheet_4 (D7.8)
X5_2_MDC_2: switch_1923KX028_v_2_sheet_3 (X5.100), switch_1923KX028_v_2_sheet_4 (D7.11)
X6_1_MDC_2: switch_1923KX028_v_2_sheet_3 (X6.40), switch_1923KX028_v_2_sheet_4 (D8.3)
X6_2_MDC_2: switch_1923KX028_v_2_sheet_3 (X6.100), switch_1923KX028_v_2_sheet_4 (D8.6)
X8_1_I2C_SCL: switch_1923KX028_v_2_sheet_4 (R230.2 X8.29), switch_1923KX028_v_2_sheet_5 (D16.12)
X8_1_I2C_SDA: switch_1923KX028_v_2_sheet_4 (R229.2 X8.31), switch_1923KX028_v_2_sheet_5 (D16.11)
X8_1_SFP_PRES: switch_1923KX028_v_2_sheet_4 (R228.2 X8.35), switch_1923KX028_v_2_sheet_5 (D11.57)
X8_2_I2C_SCL: switch_1923KX028_v_2_sheet_4 (R233.2 X8.89), switch_1923KX028_v_2_sheet_5 (D16.7)
X8_2_I2C_SDA: switch_1923KX028_v_2_sheet_4 (R232.2 X8.91), switch_1923KX028_v_2_sheet_5 (D16.6)
X8_2_SFP_PRES: switch_1923KX028_v_2_sheet_4 (R231.2 X8.95), switch_1923KX028_v_2_sheet_5 (D11.56)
